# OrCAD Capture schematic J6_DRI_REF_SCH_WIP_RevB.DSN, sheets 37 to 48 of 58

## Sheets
37 SH40 - VIDEO OUT FPD LINK: size B; rev: A
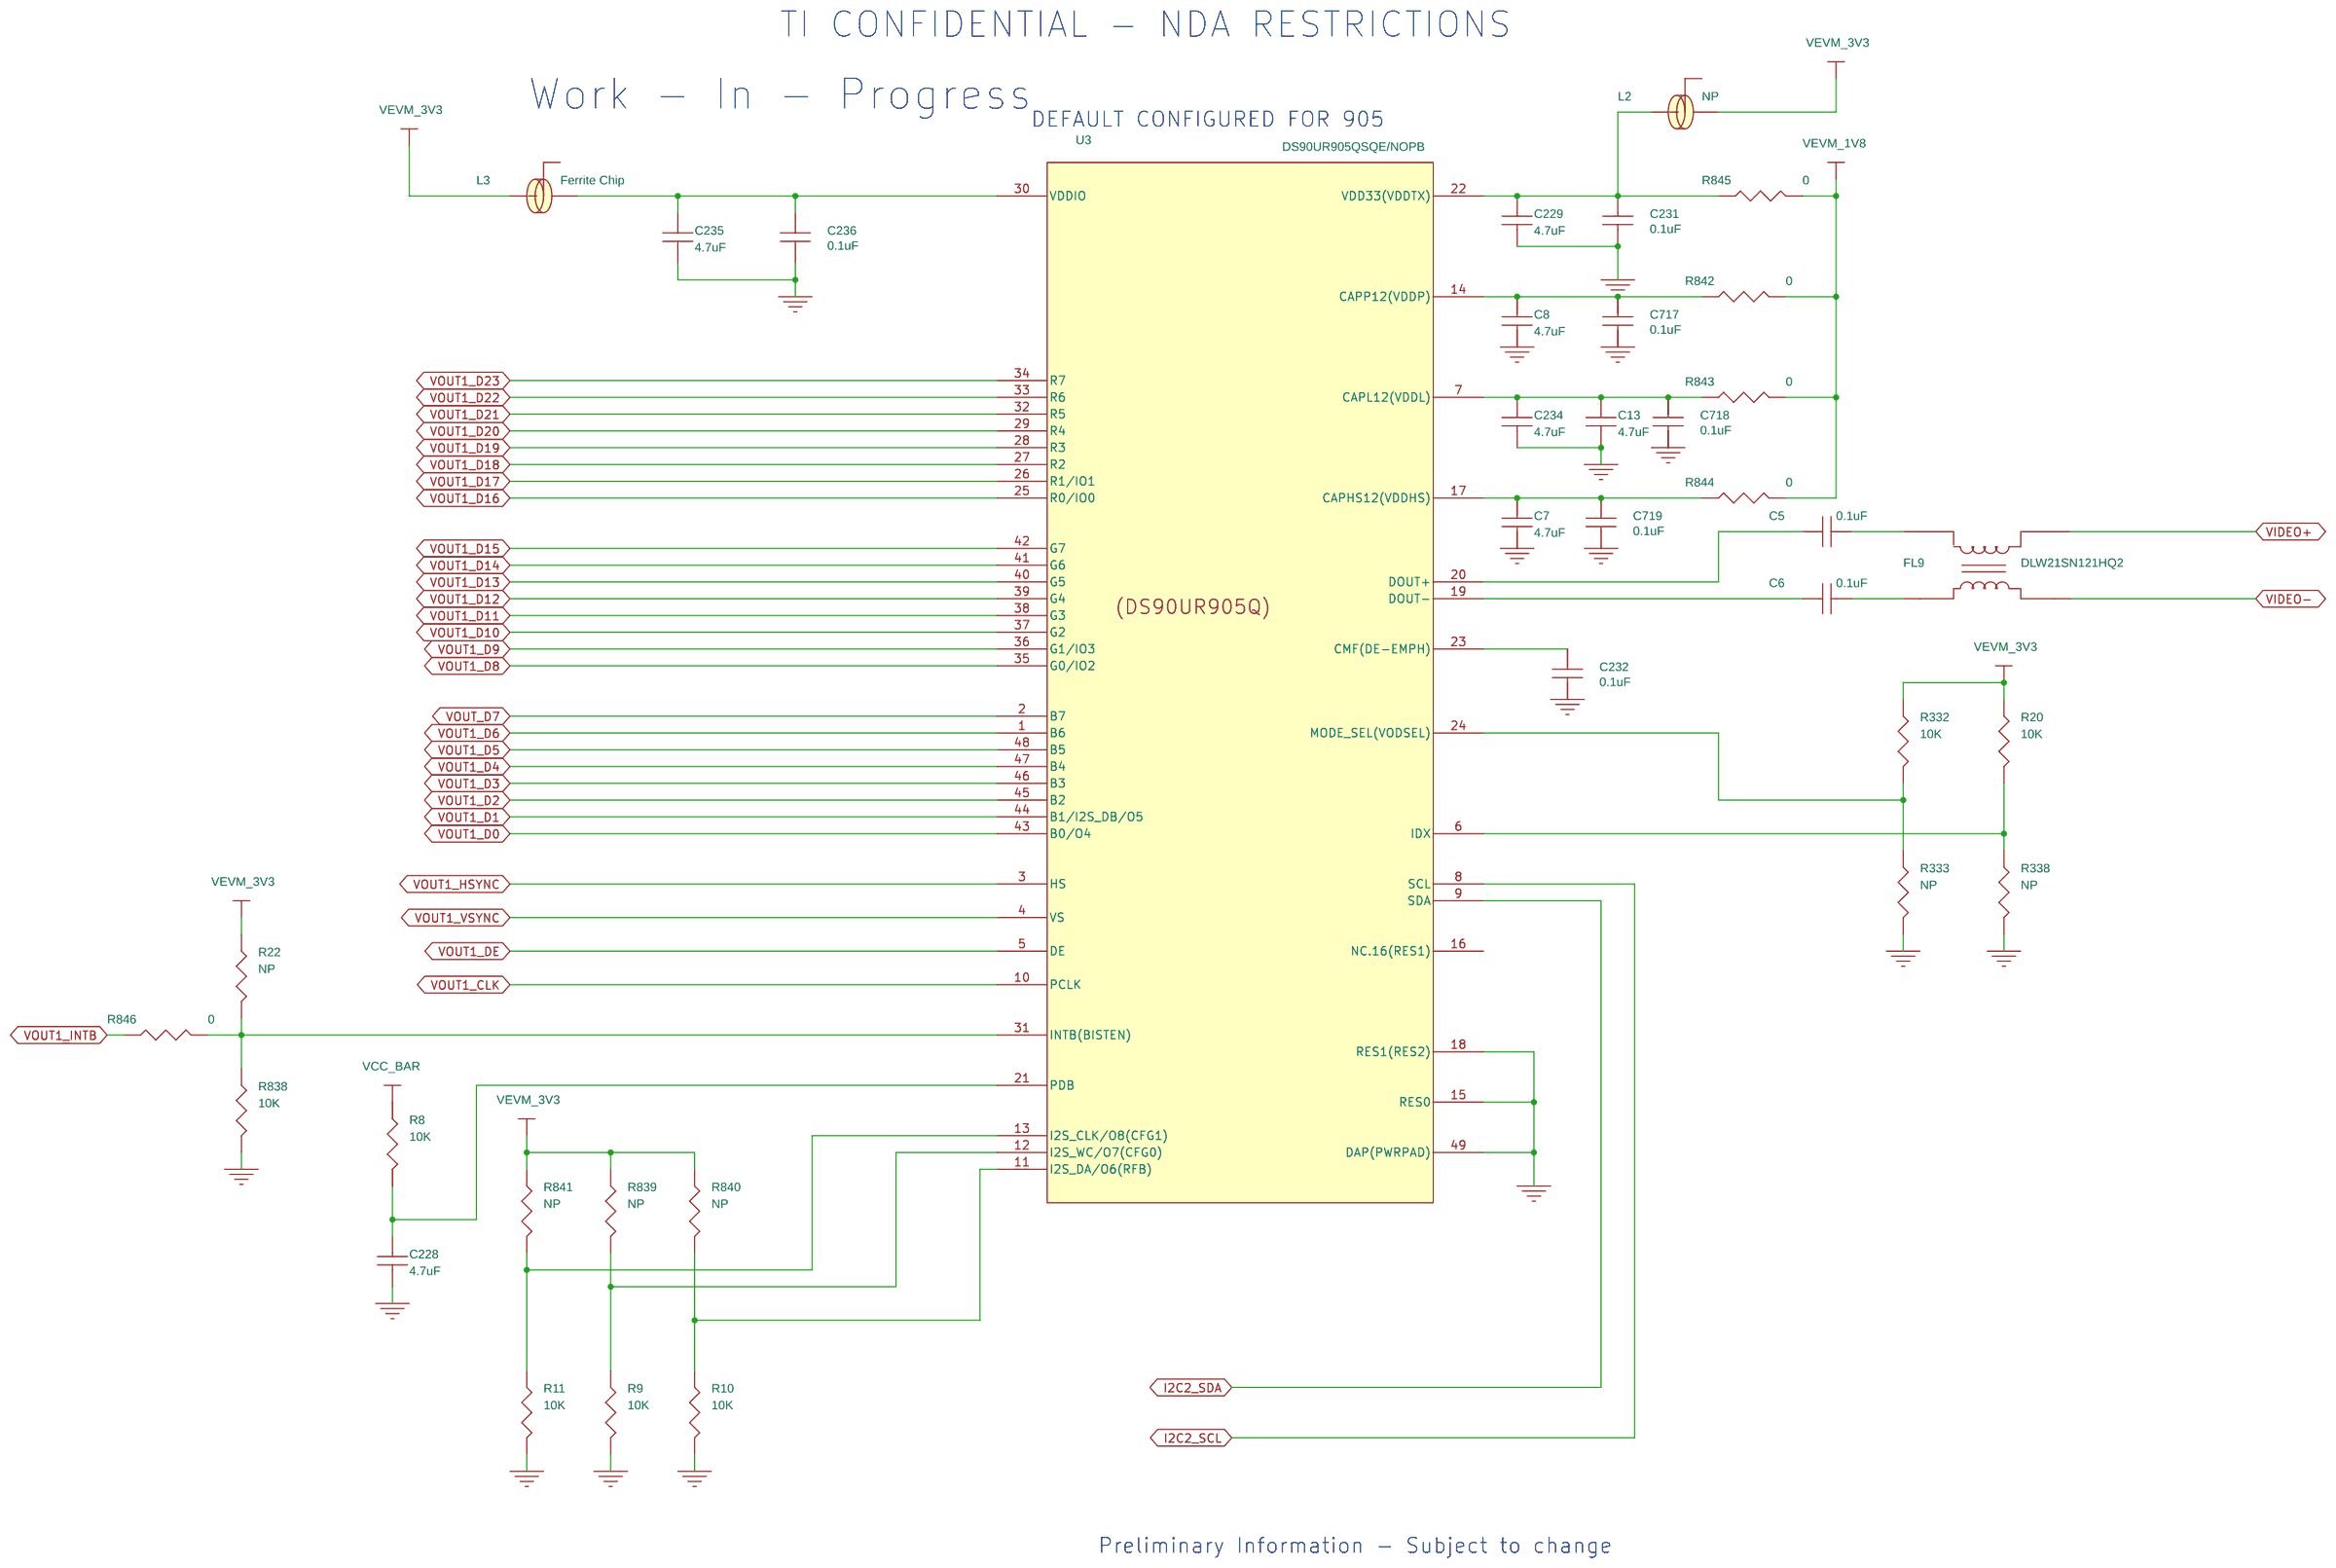
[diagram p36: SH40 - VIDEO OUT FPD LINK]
38 SH41 - VIDEO IN: size B; rev: A
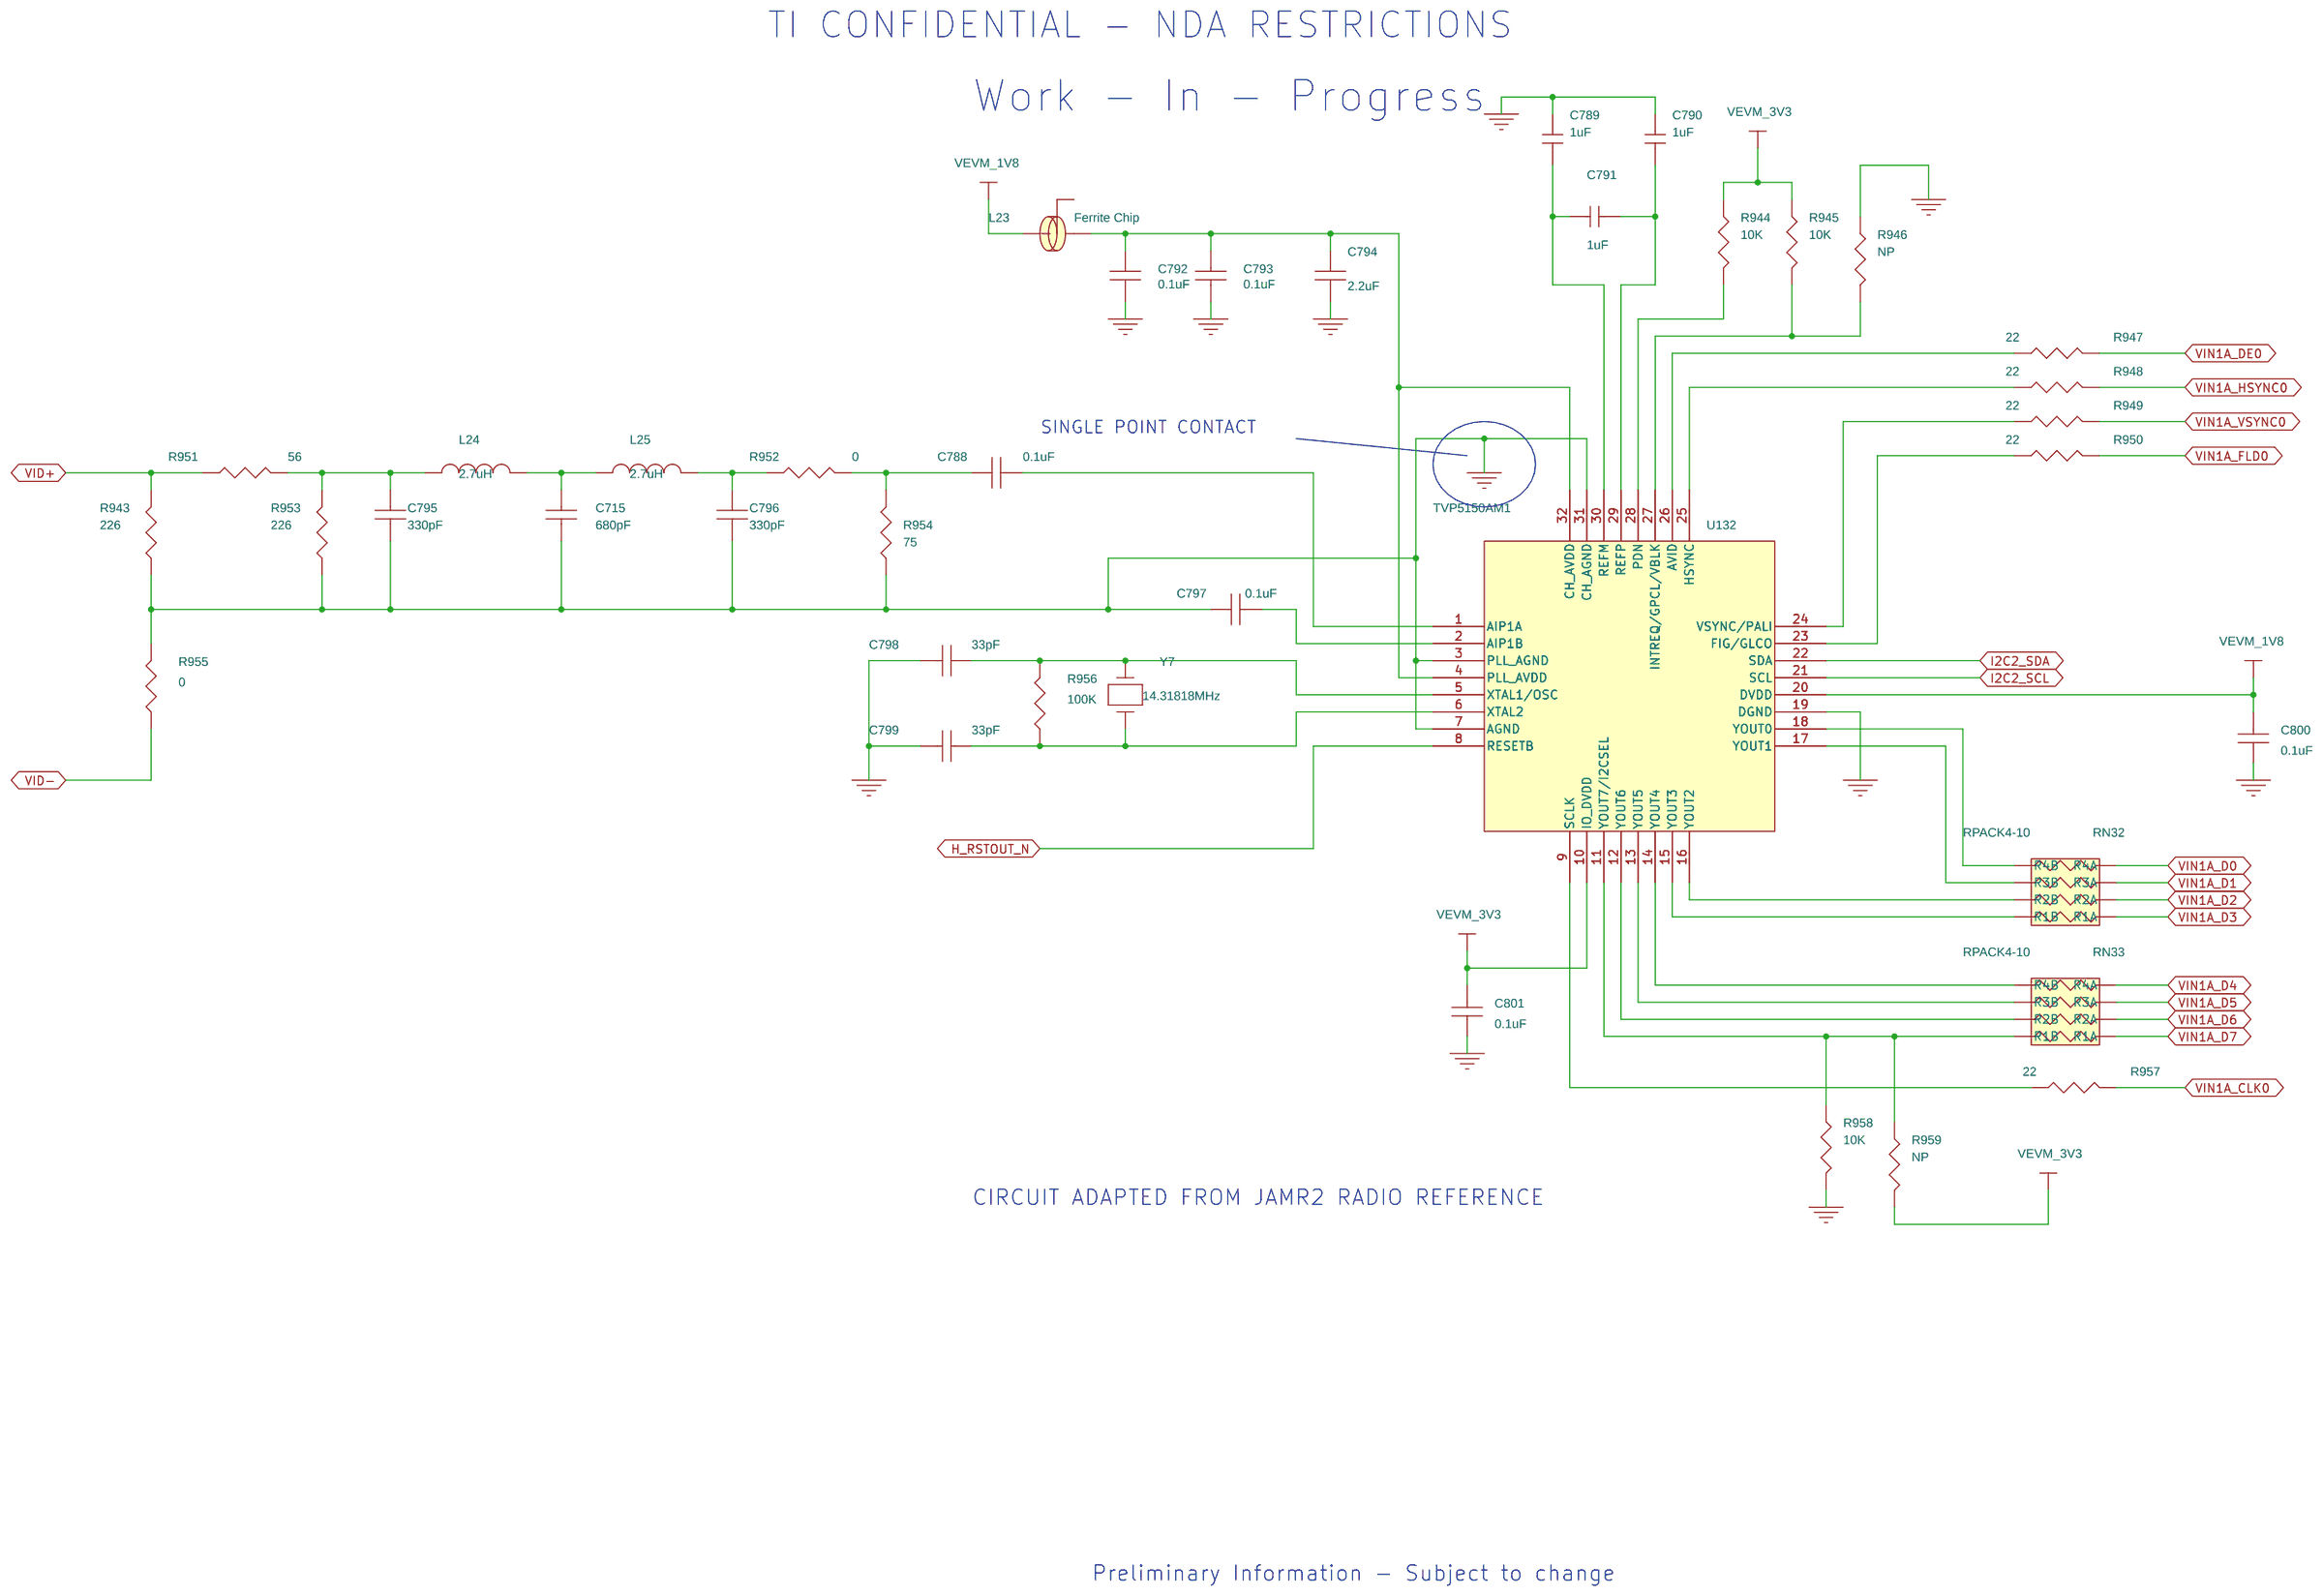
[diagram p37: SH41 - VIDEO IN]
39 SH42 - AUDIO CO-DEC: size B; rev: A
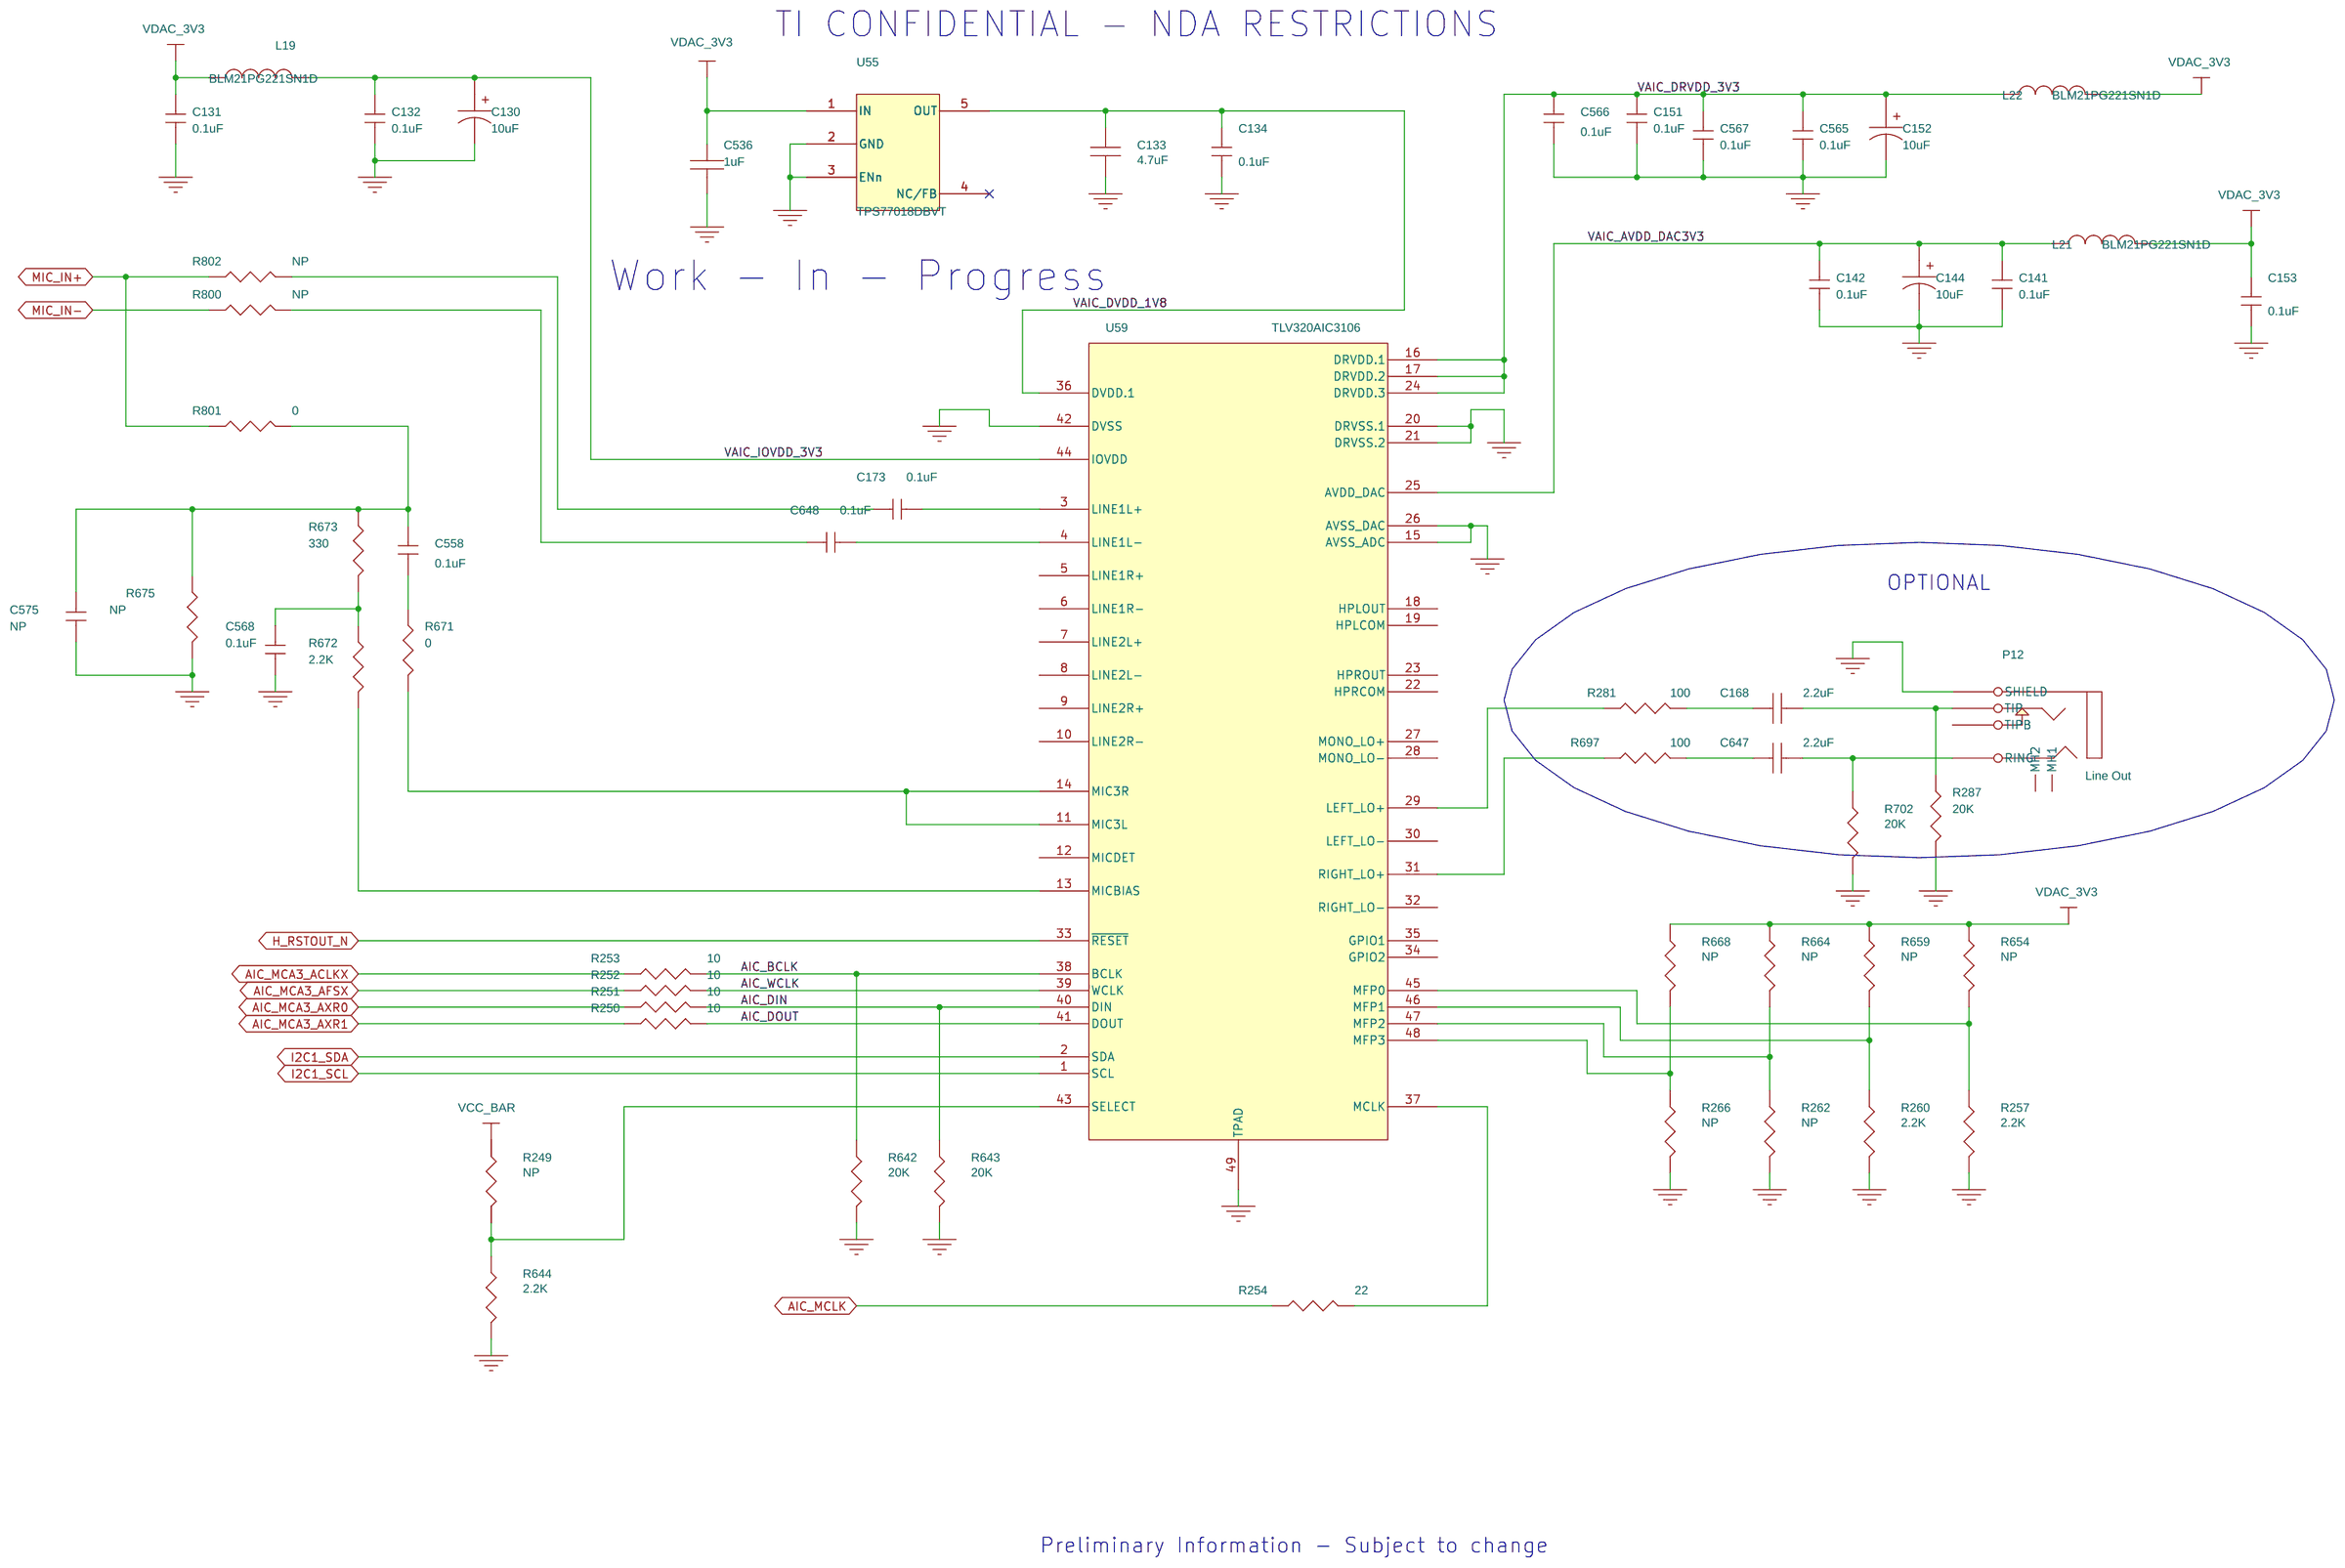
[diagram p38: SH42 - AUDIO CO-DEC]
40 SH43 - PMIC CONTROL: size B; rev: A
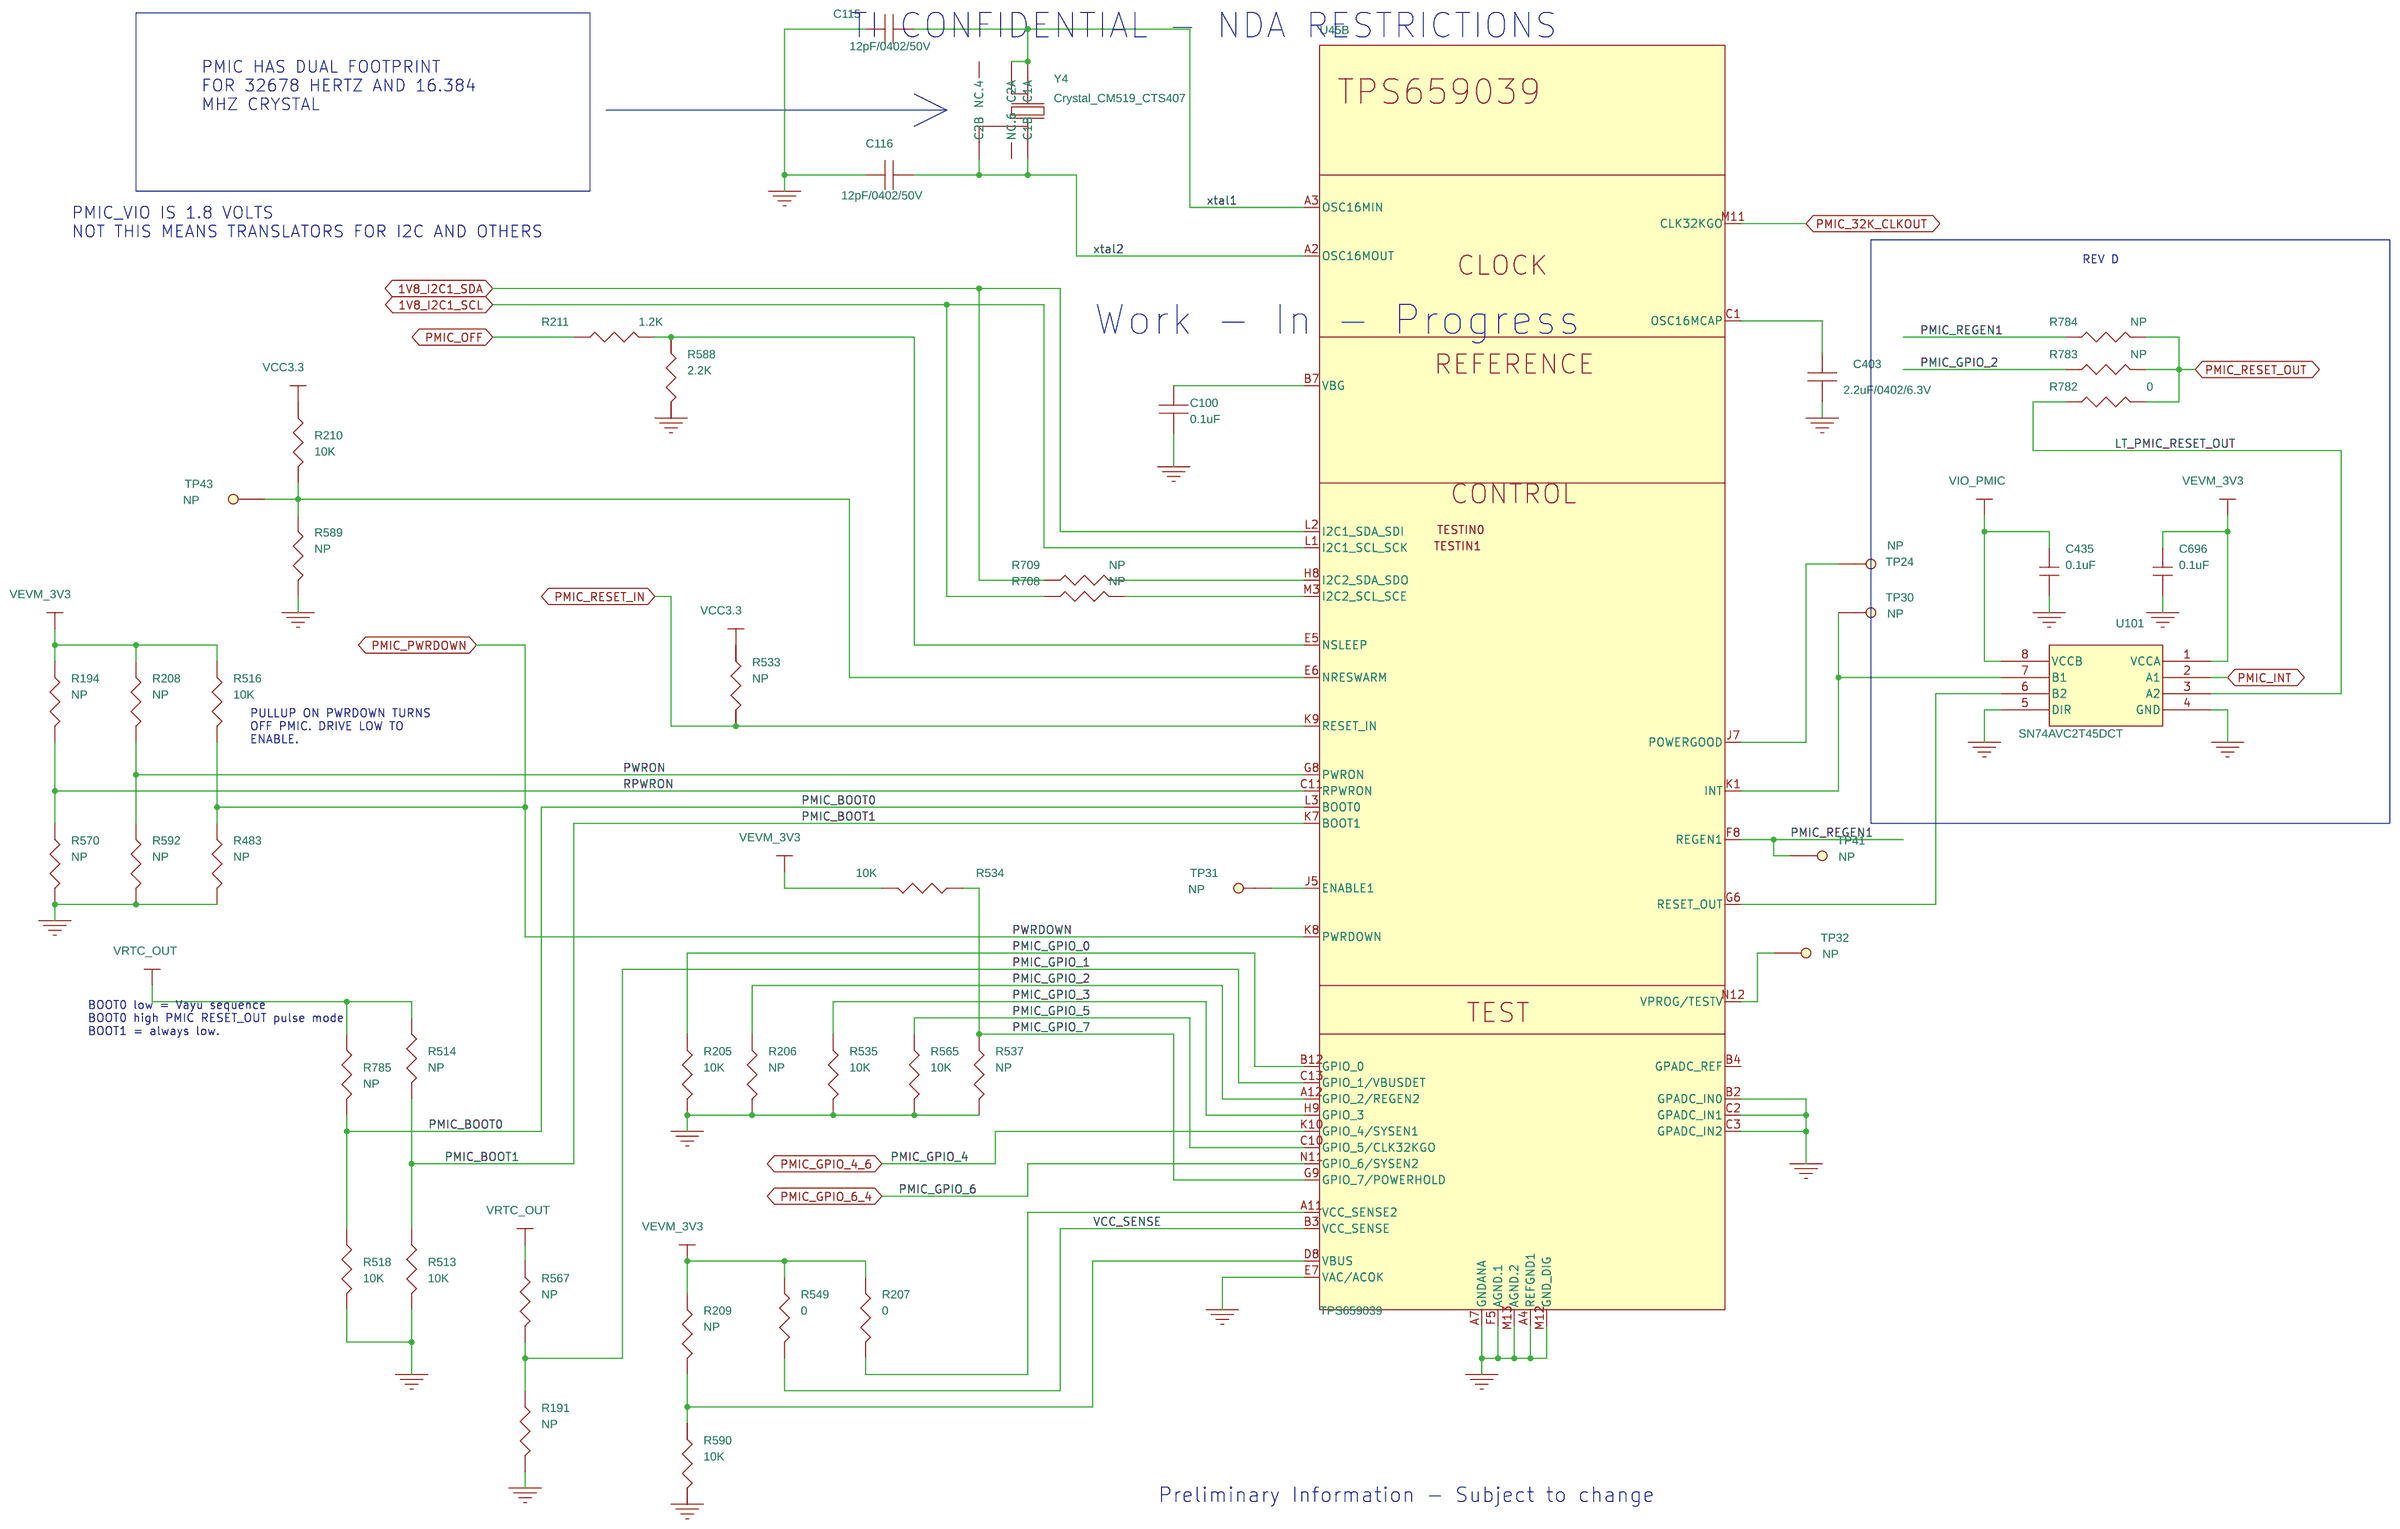
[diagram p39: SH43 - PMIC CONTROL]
41 SH44 - PMIC LDOS: size B; rev: A
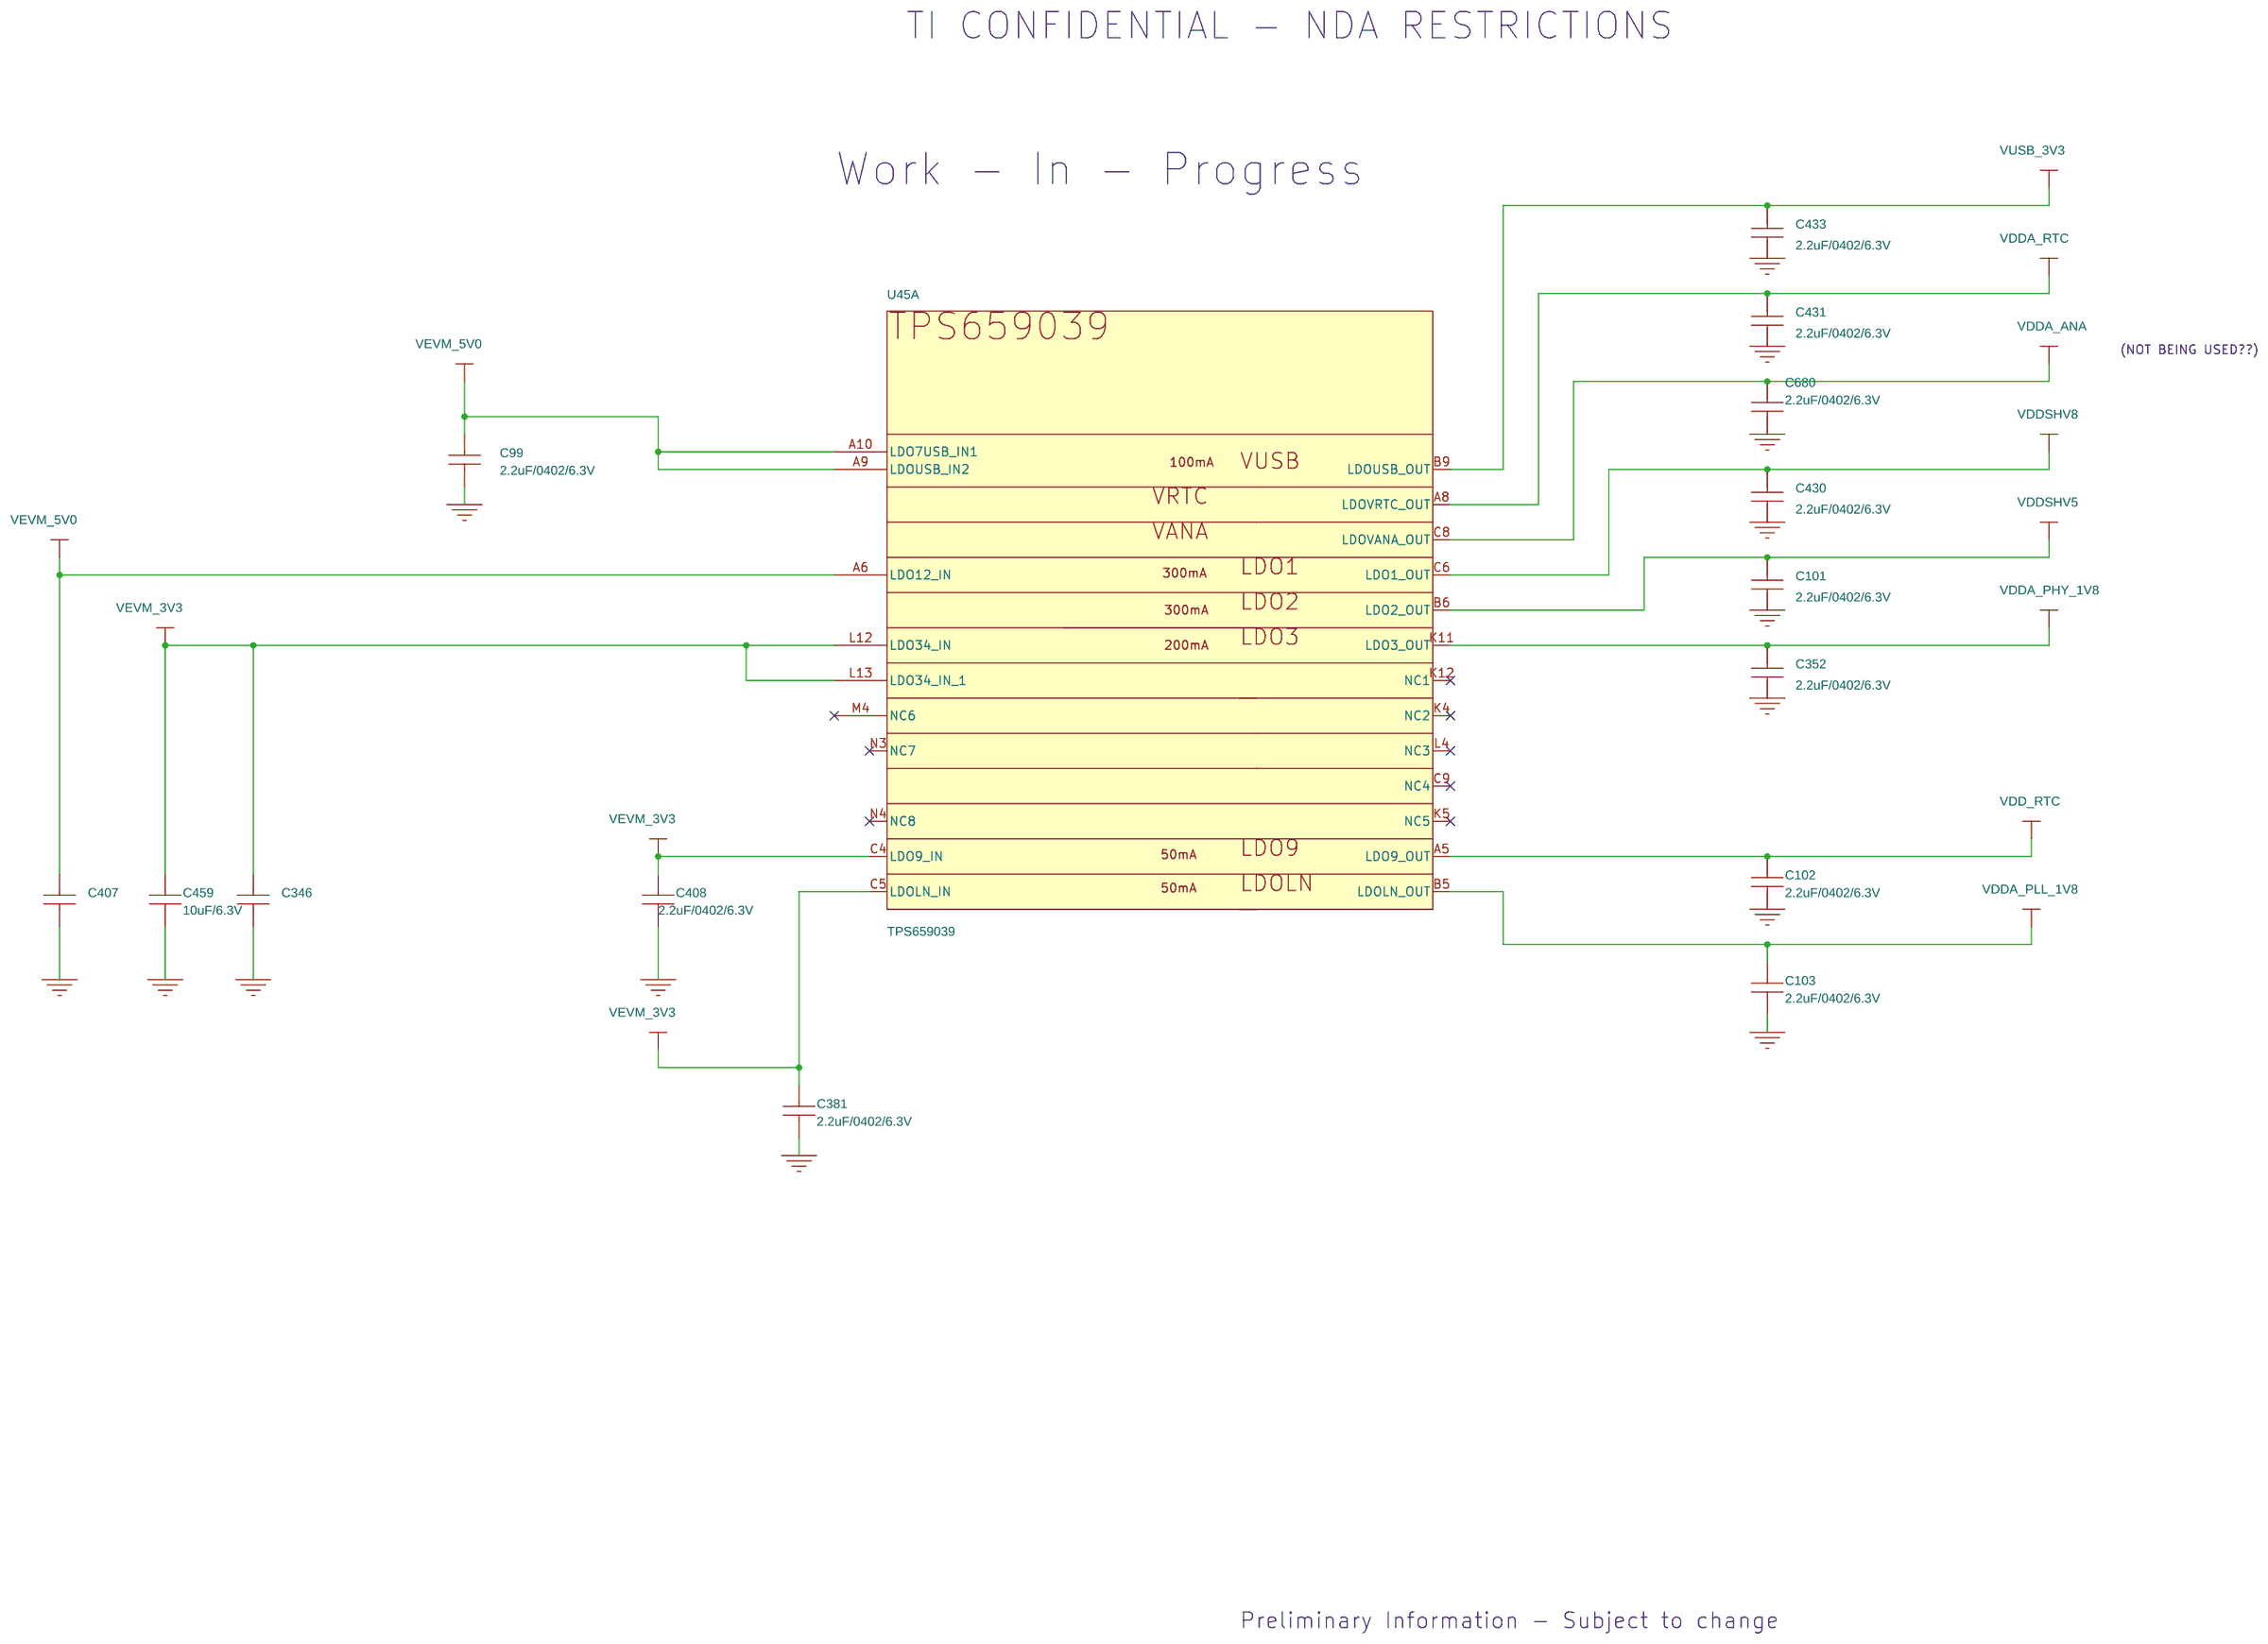
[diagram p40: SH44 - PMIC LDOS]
42 SH45 - PMIC SMPS1-5: size B; rev: A
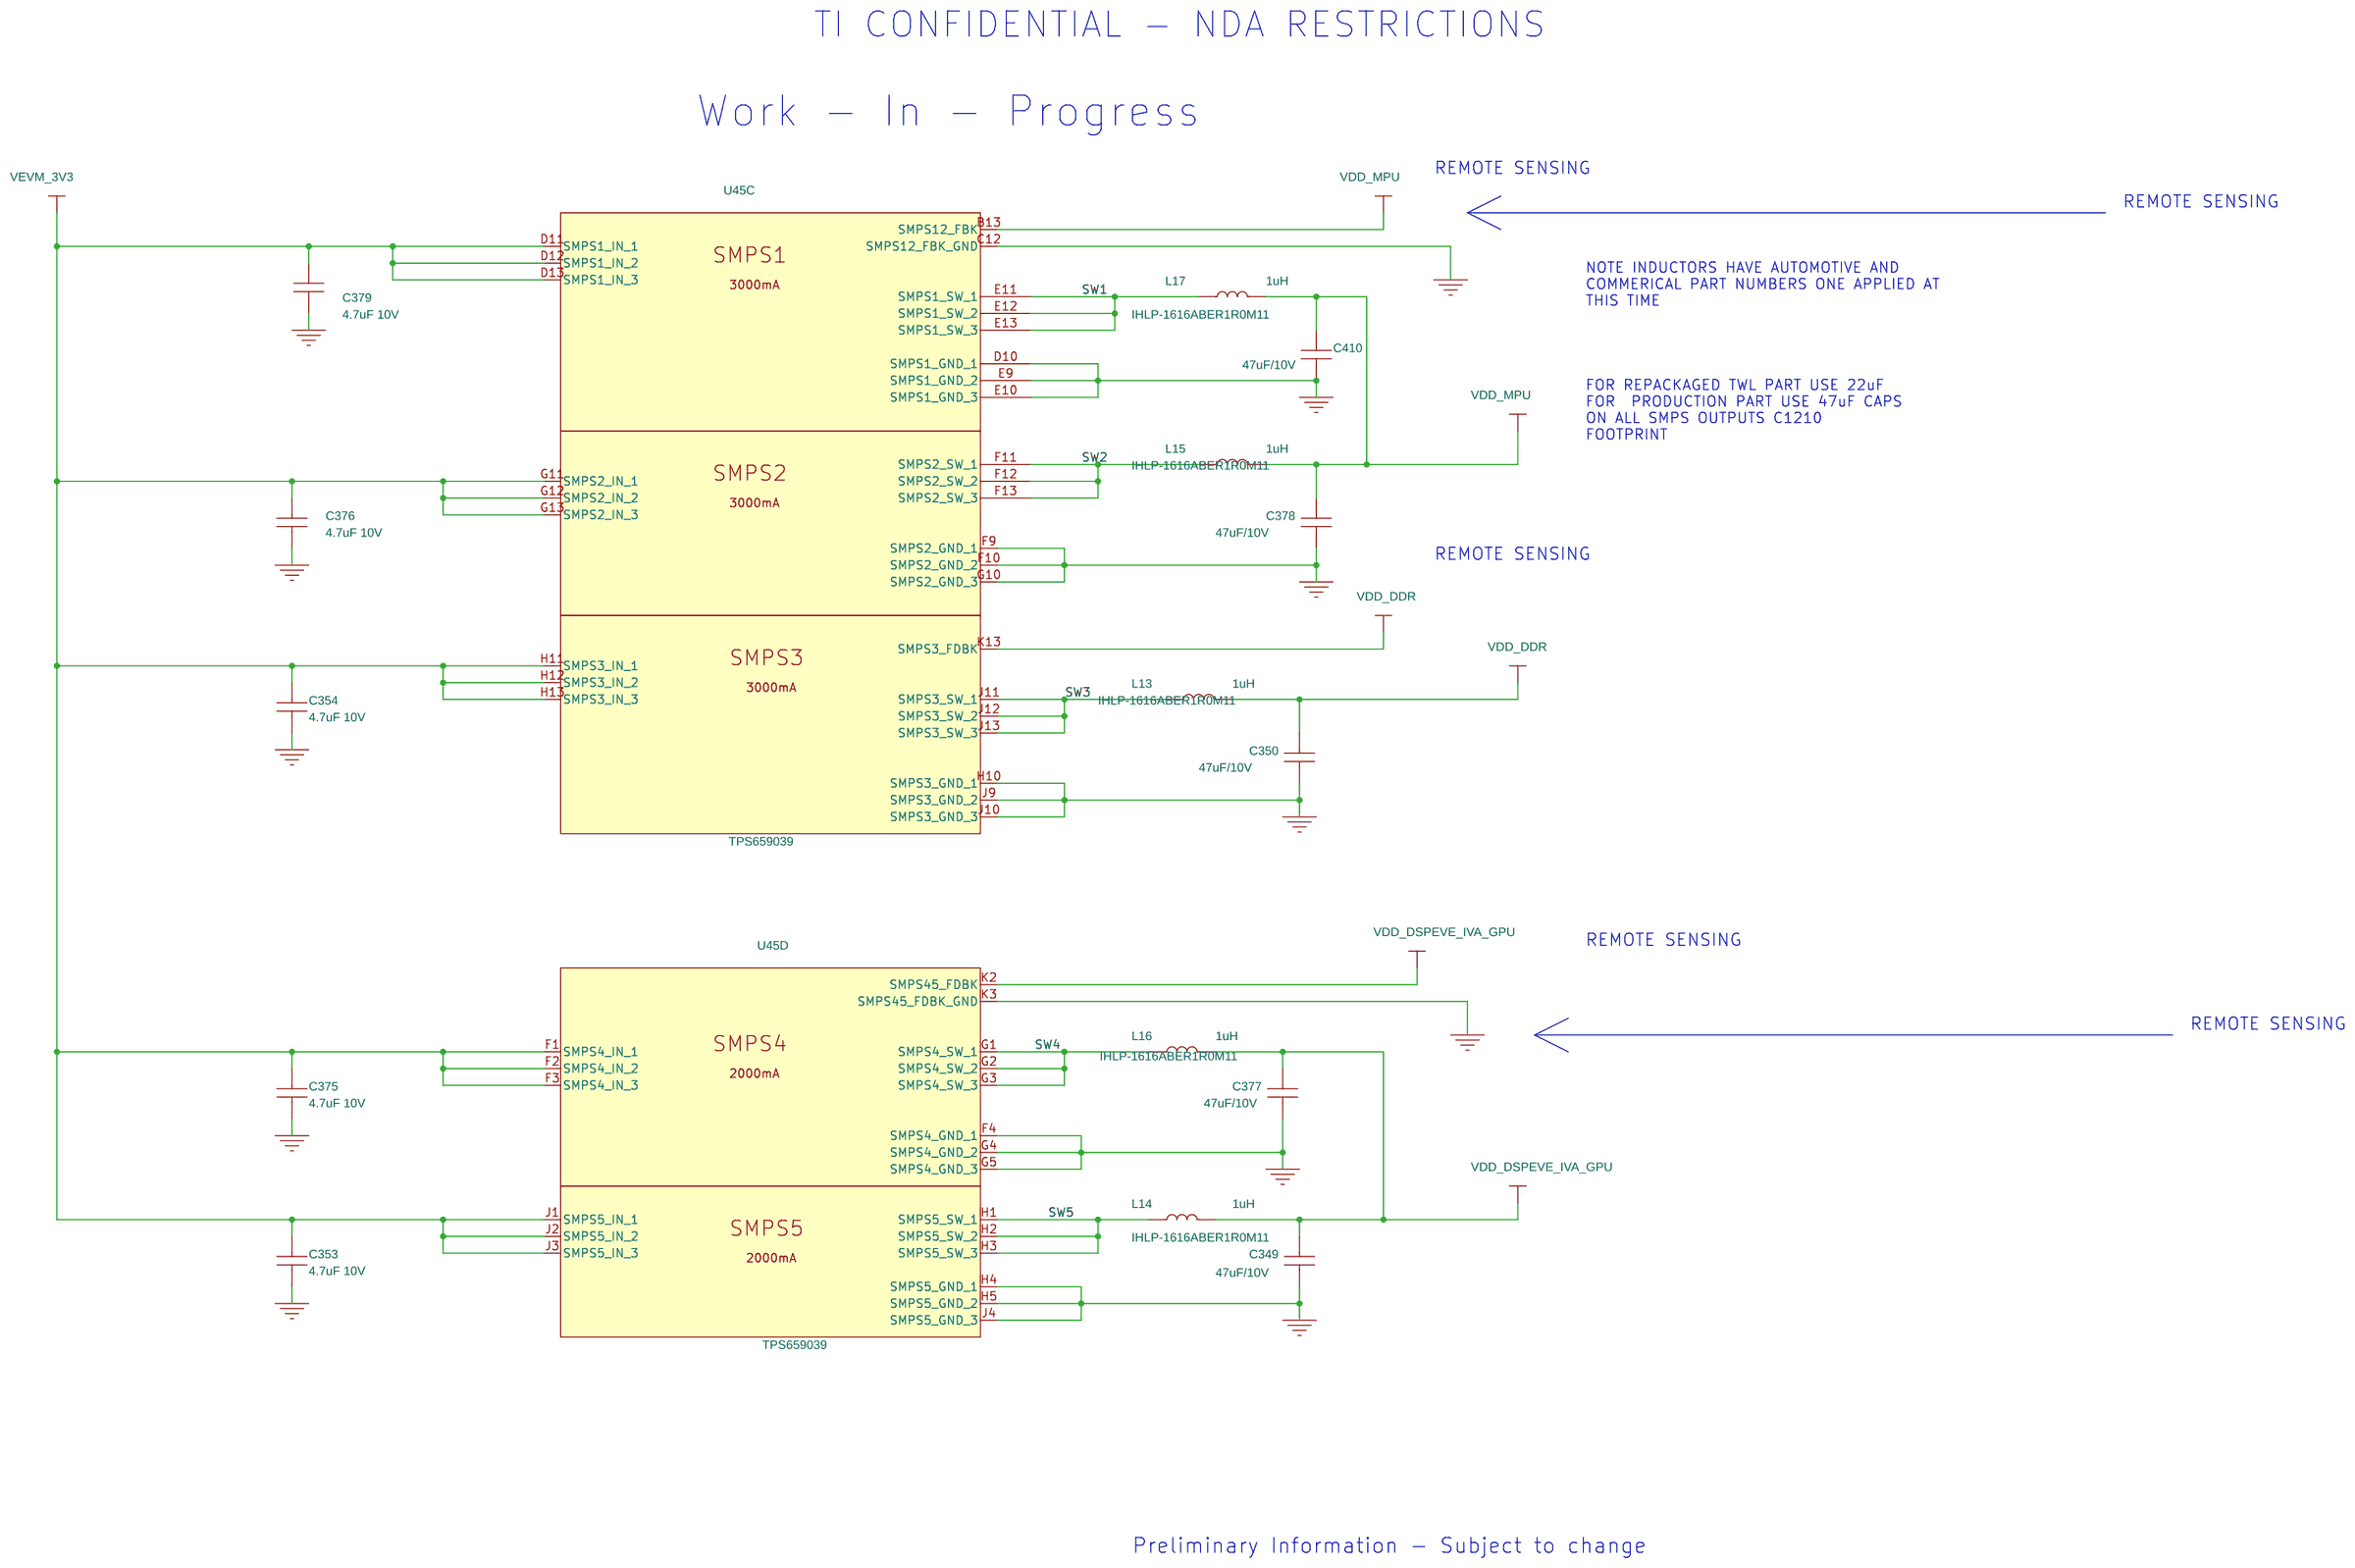
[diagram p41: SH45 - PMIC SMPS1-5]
43 SH46 - PMIC SMPS6-9 INT POWER: size B; rev: A
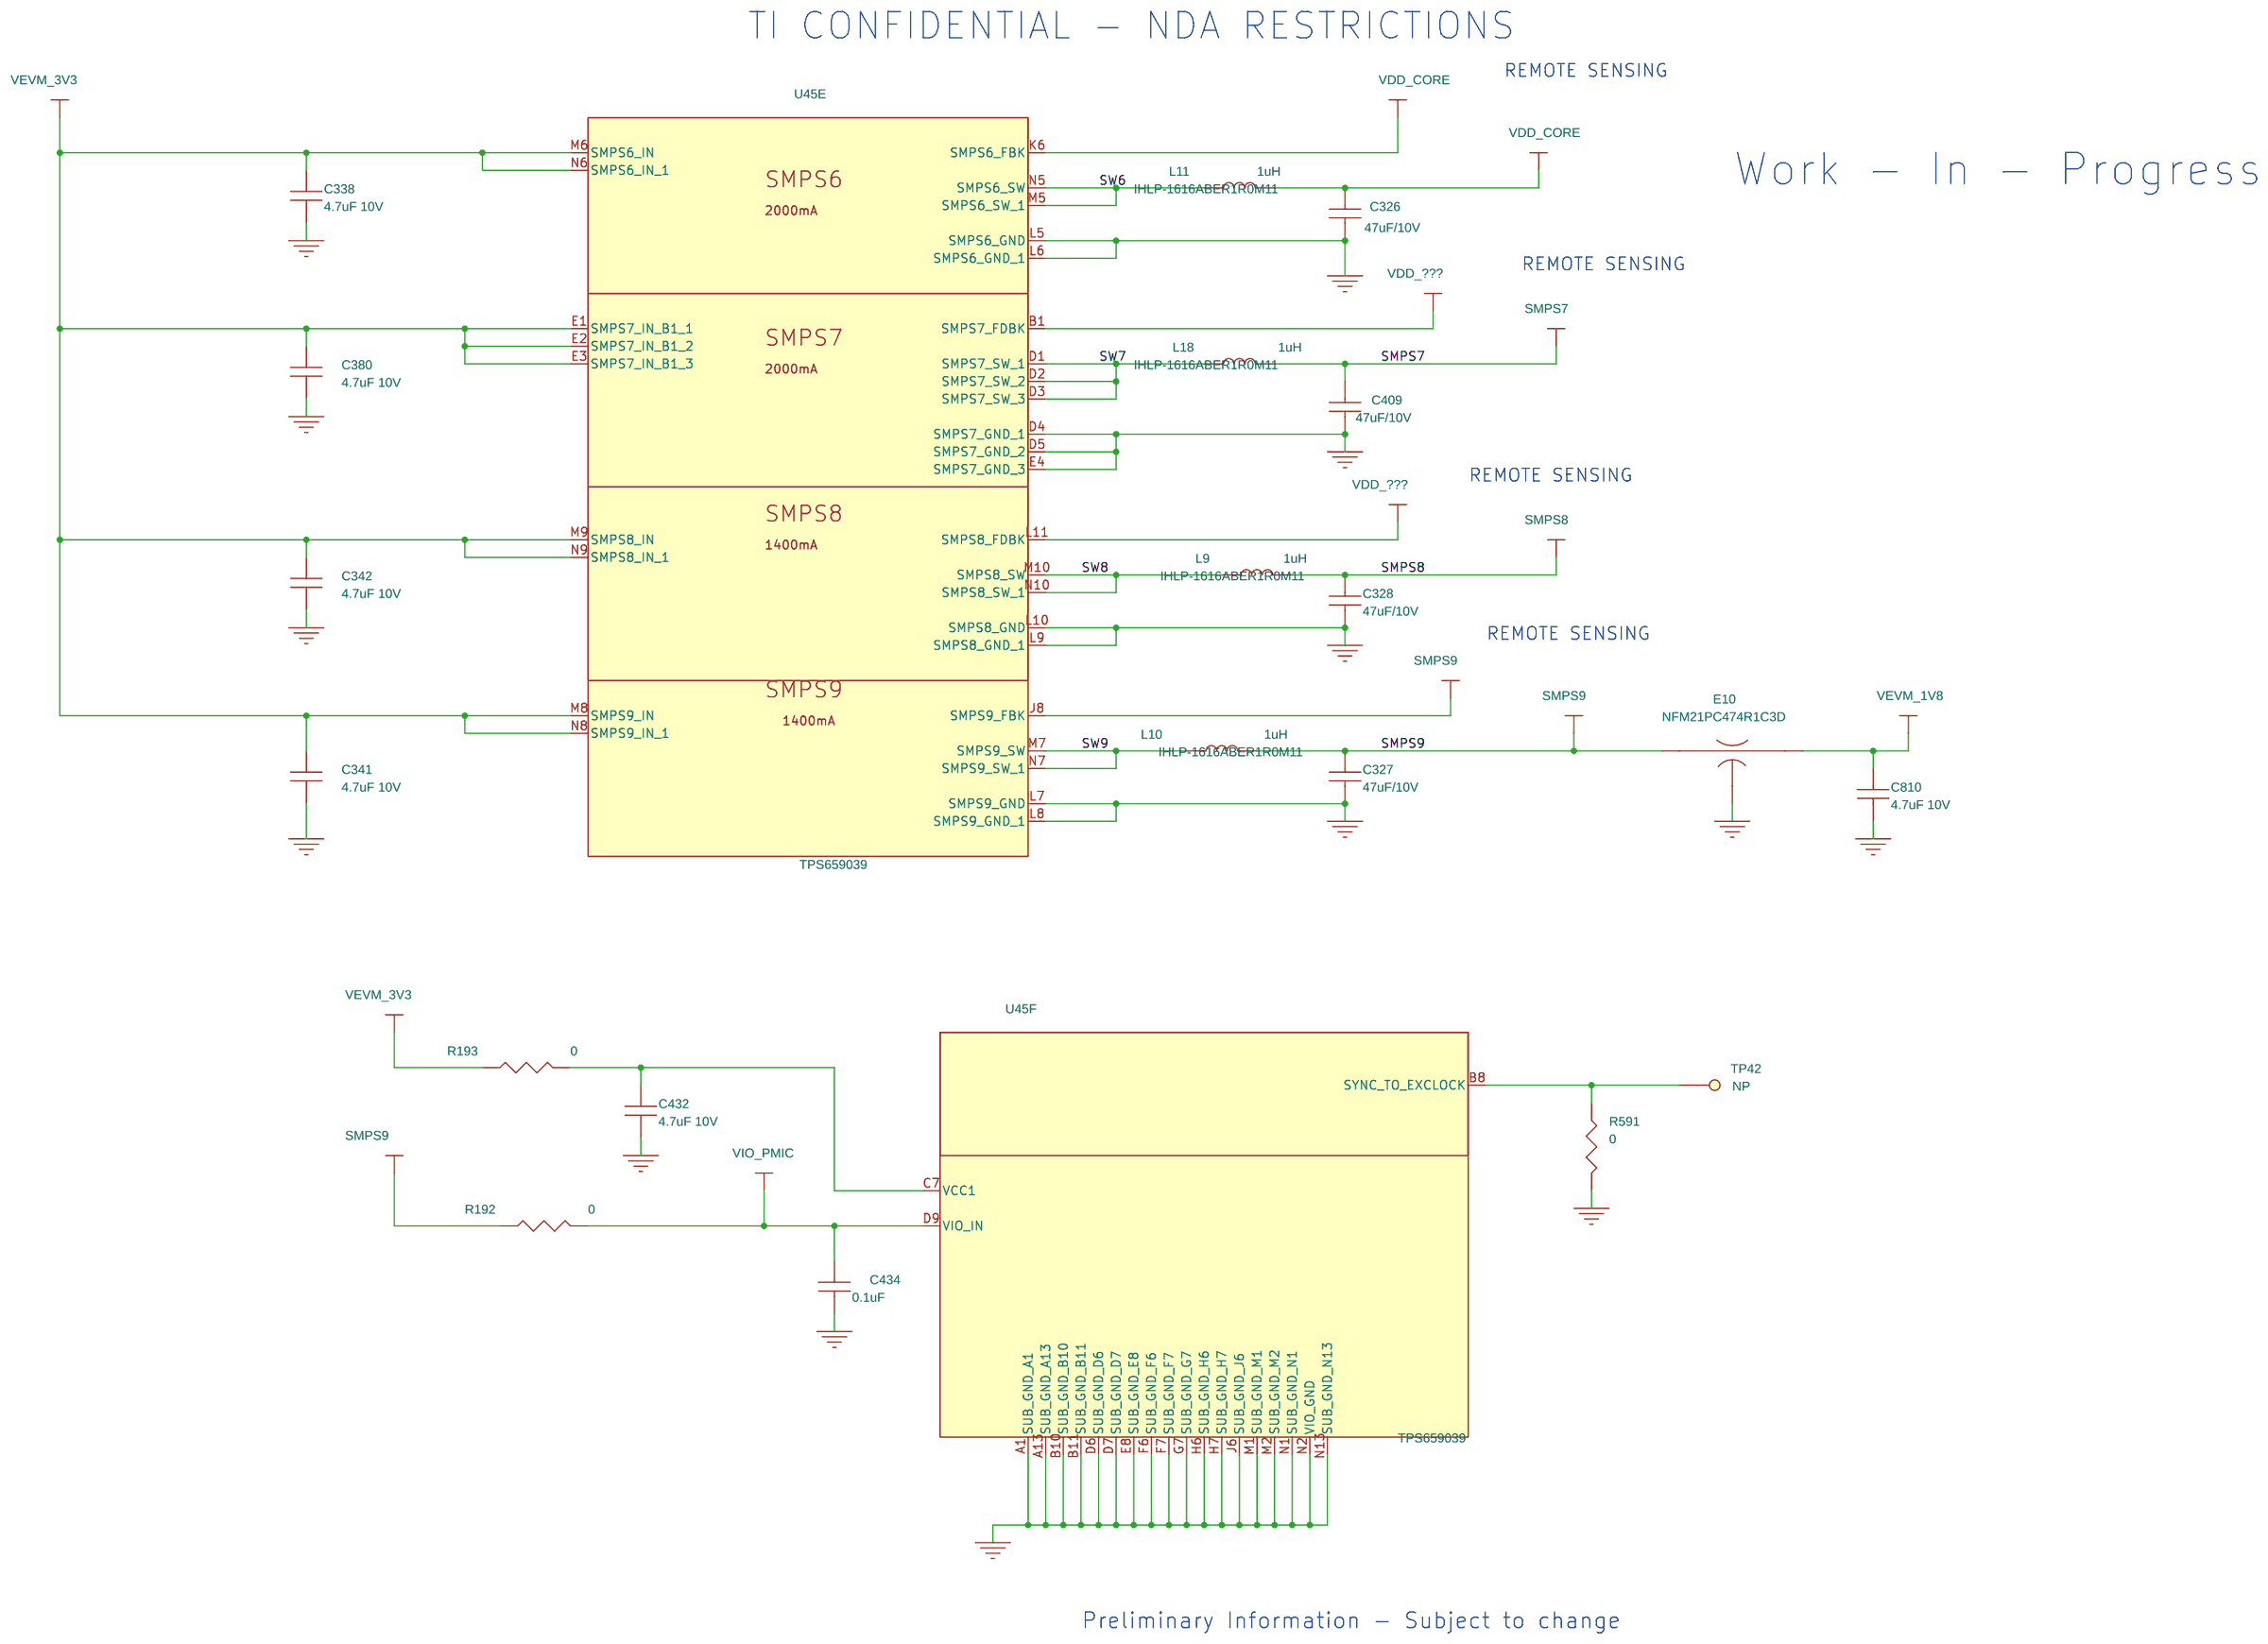
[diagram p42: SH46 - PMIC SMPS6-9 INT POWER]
44 SH47 - RESET GENERATION: size B; rev: A
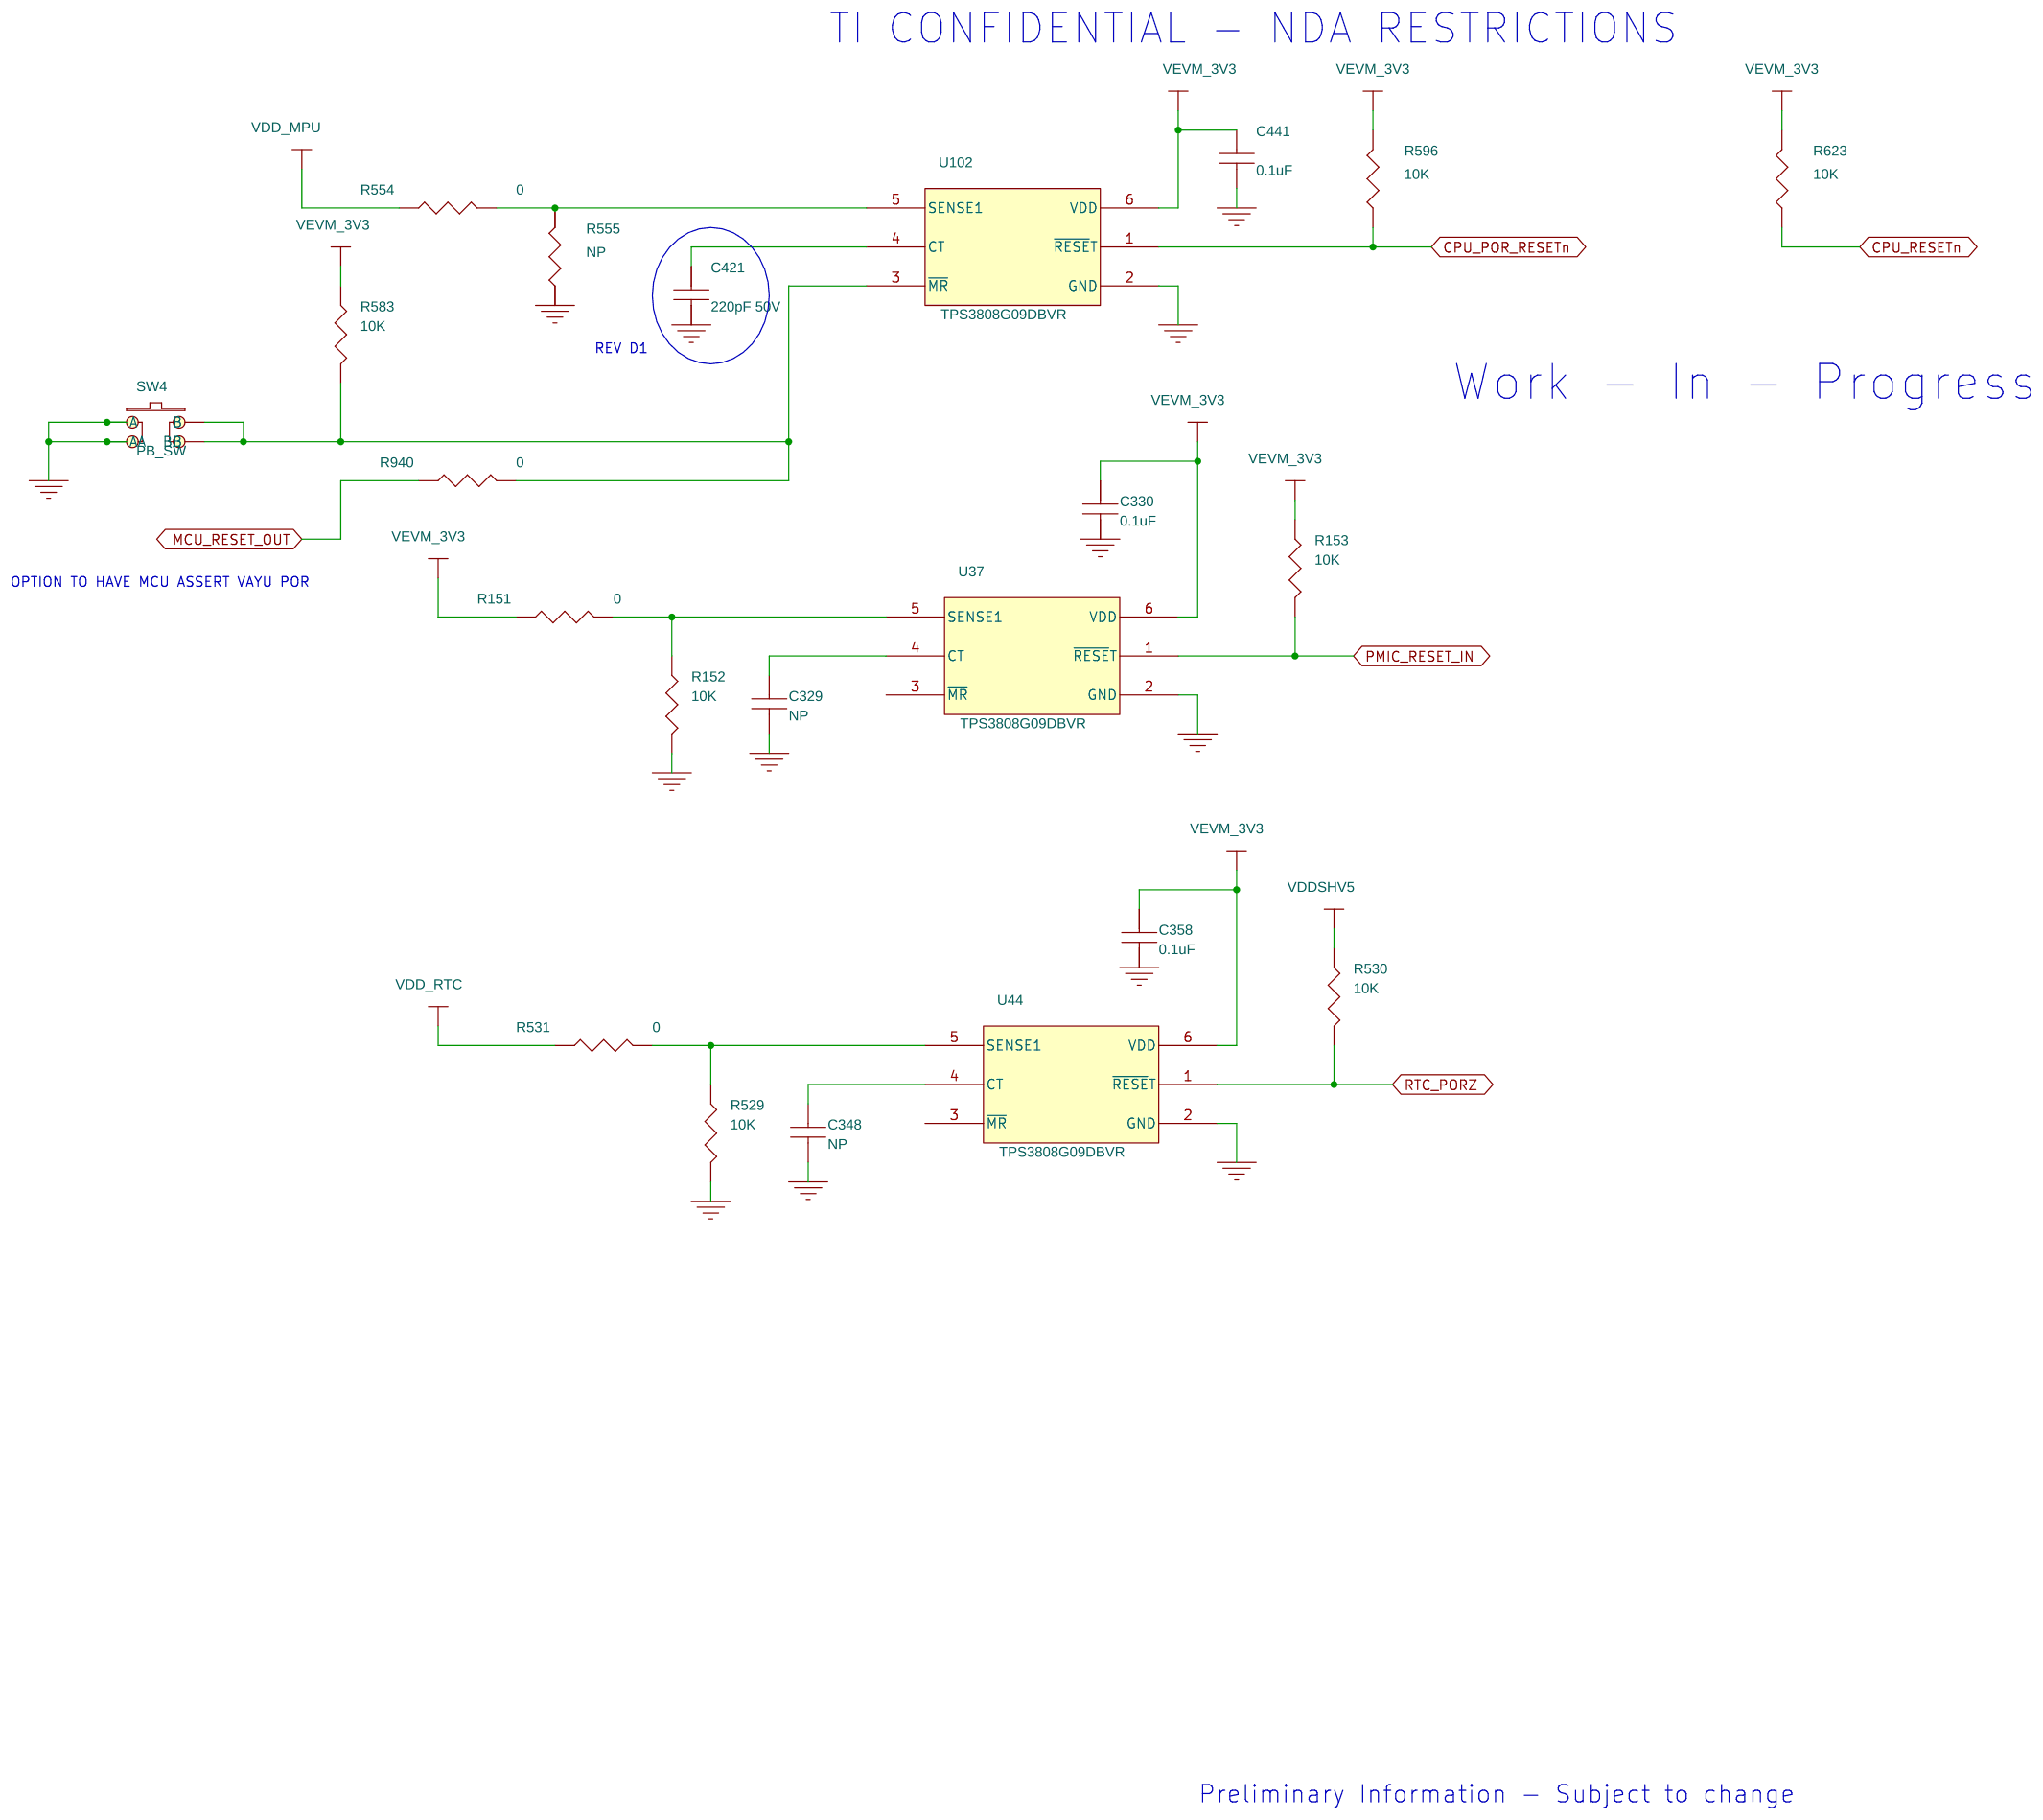
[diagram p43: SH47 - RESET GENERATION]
45 SH48 - SOC BOOT SETTINGS: size B; rev: A
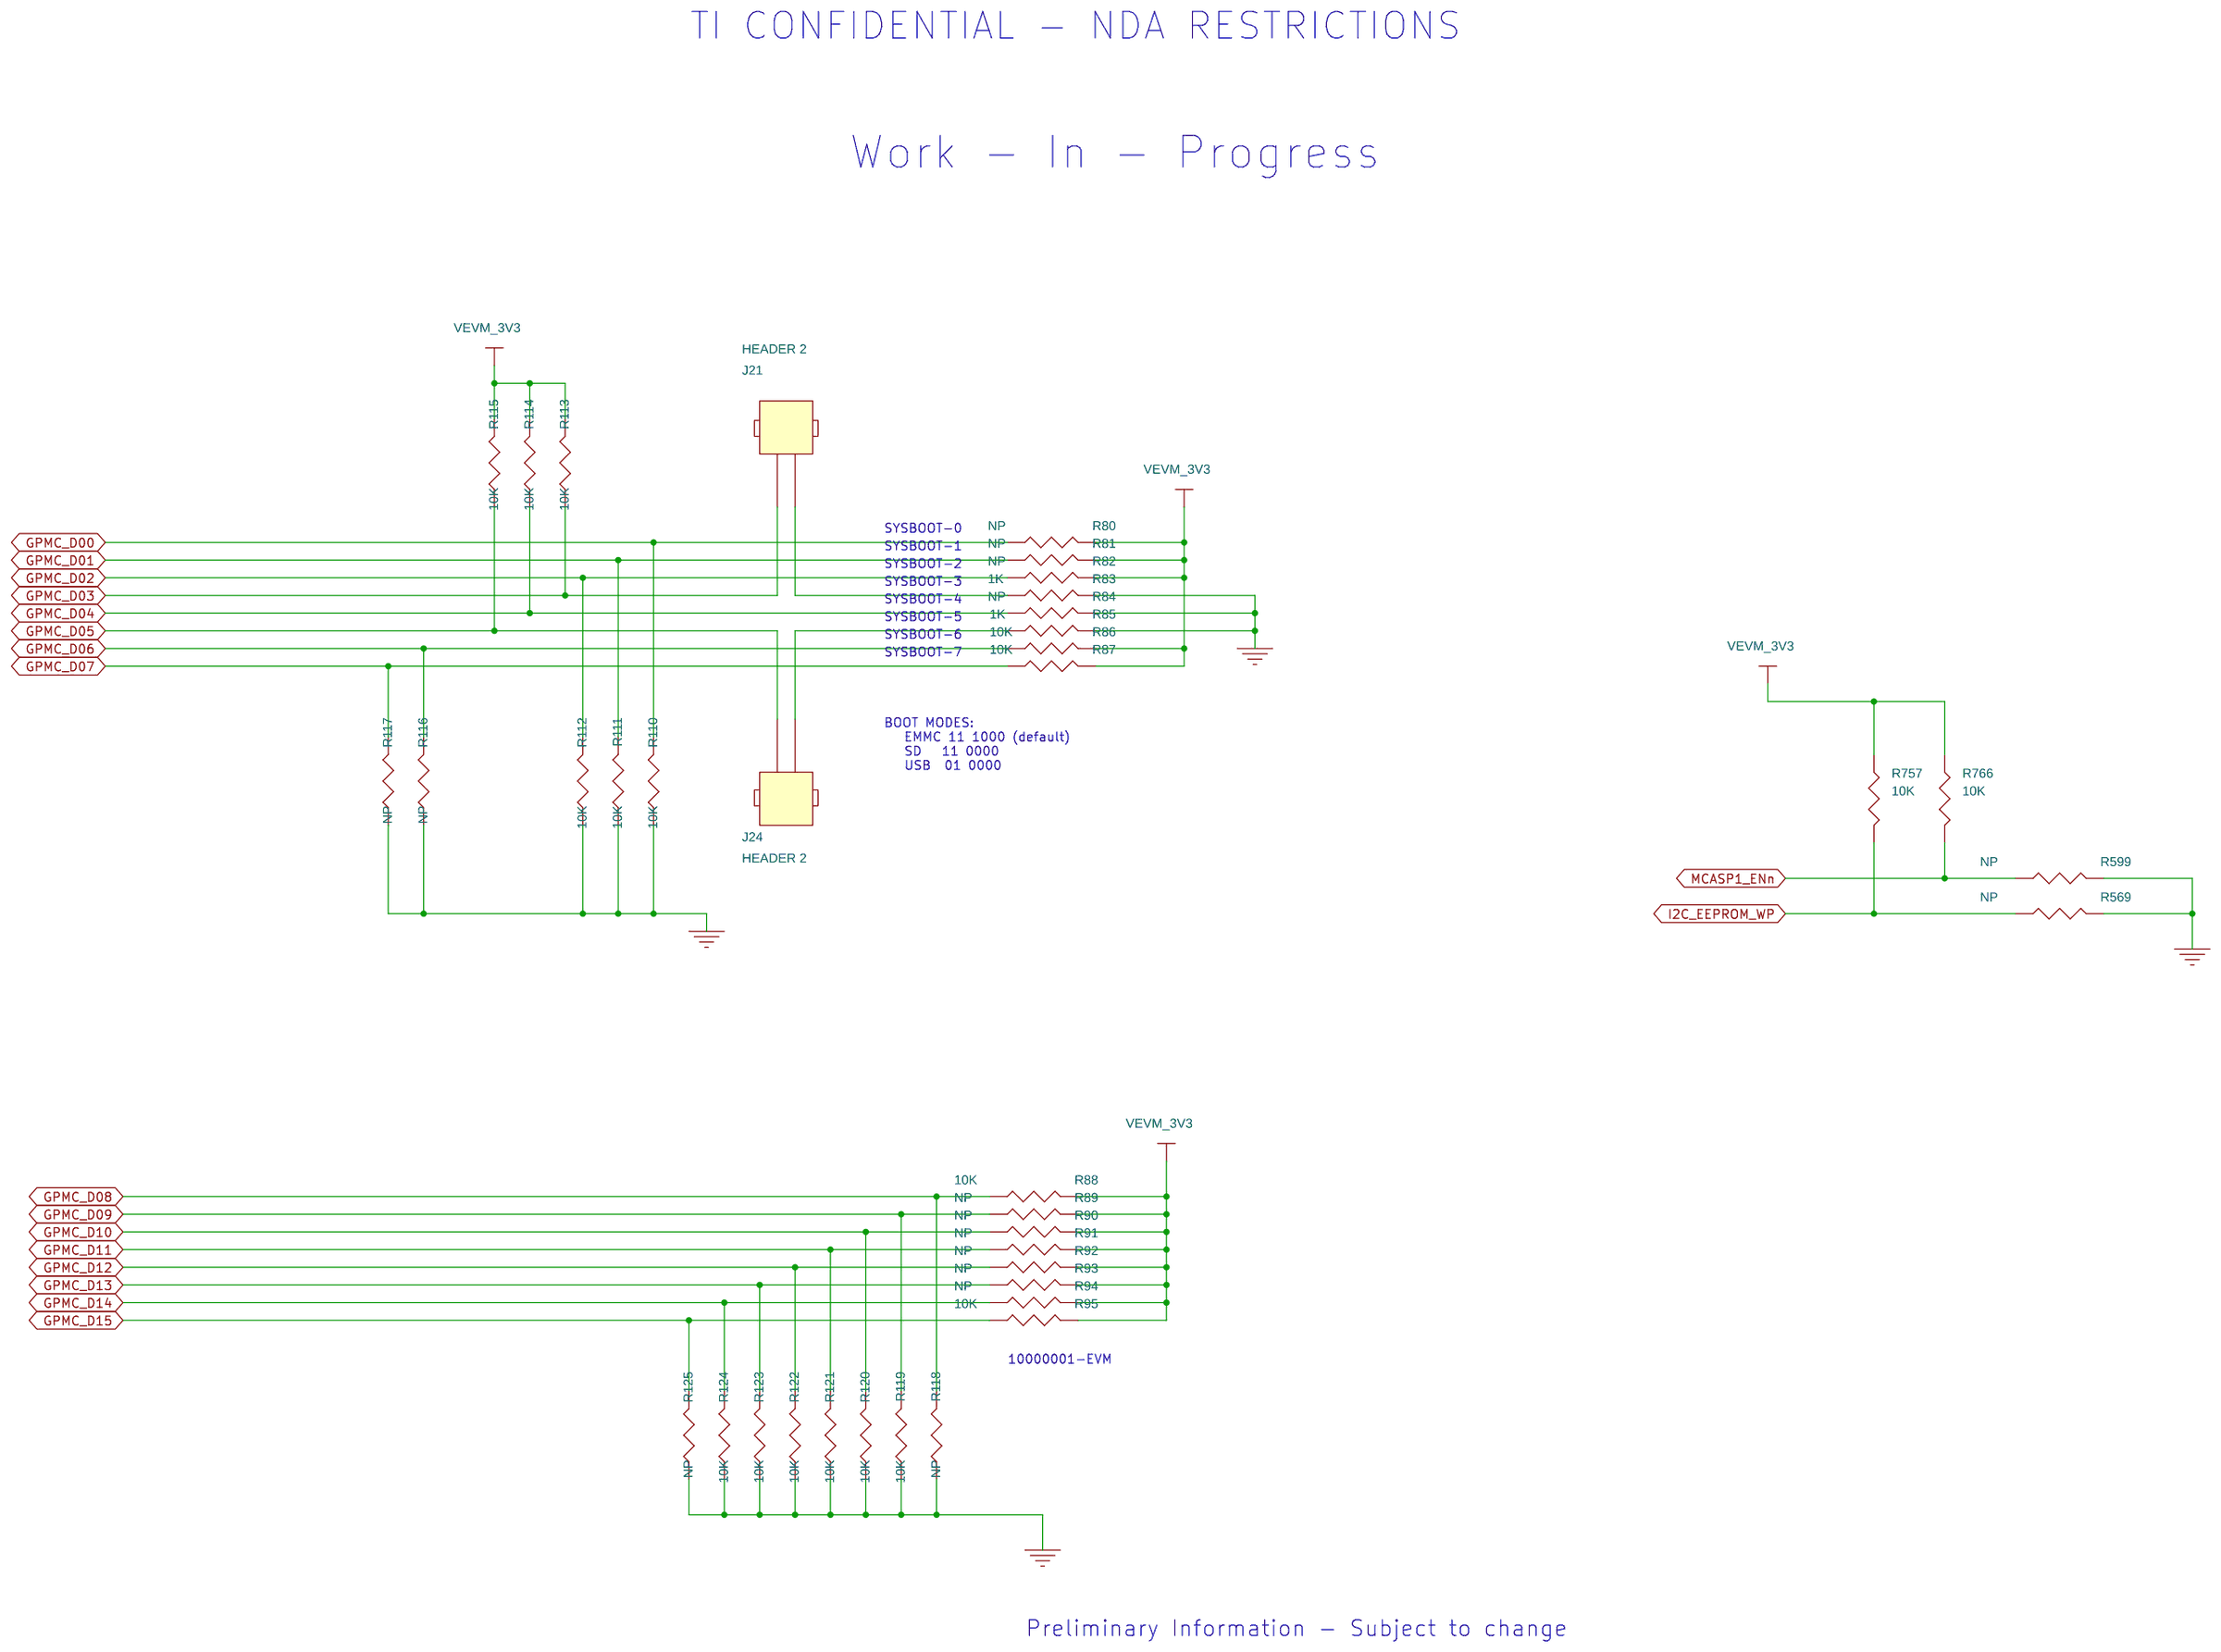
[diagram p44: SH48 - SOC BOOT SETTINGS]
46 SH49 - DEBUG: size B; rev: A
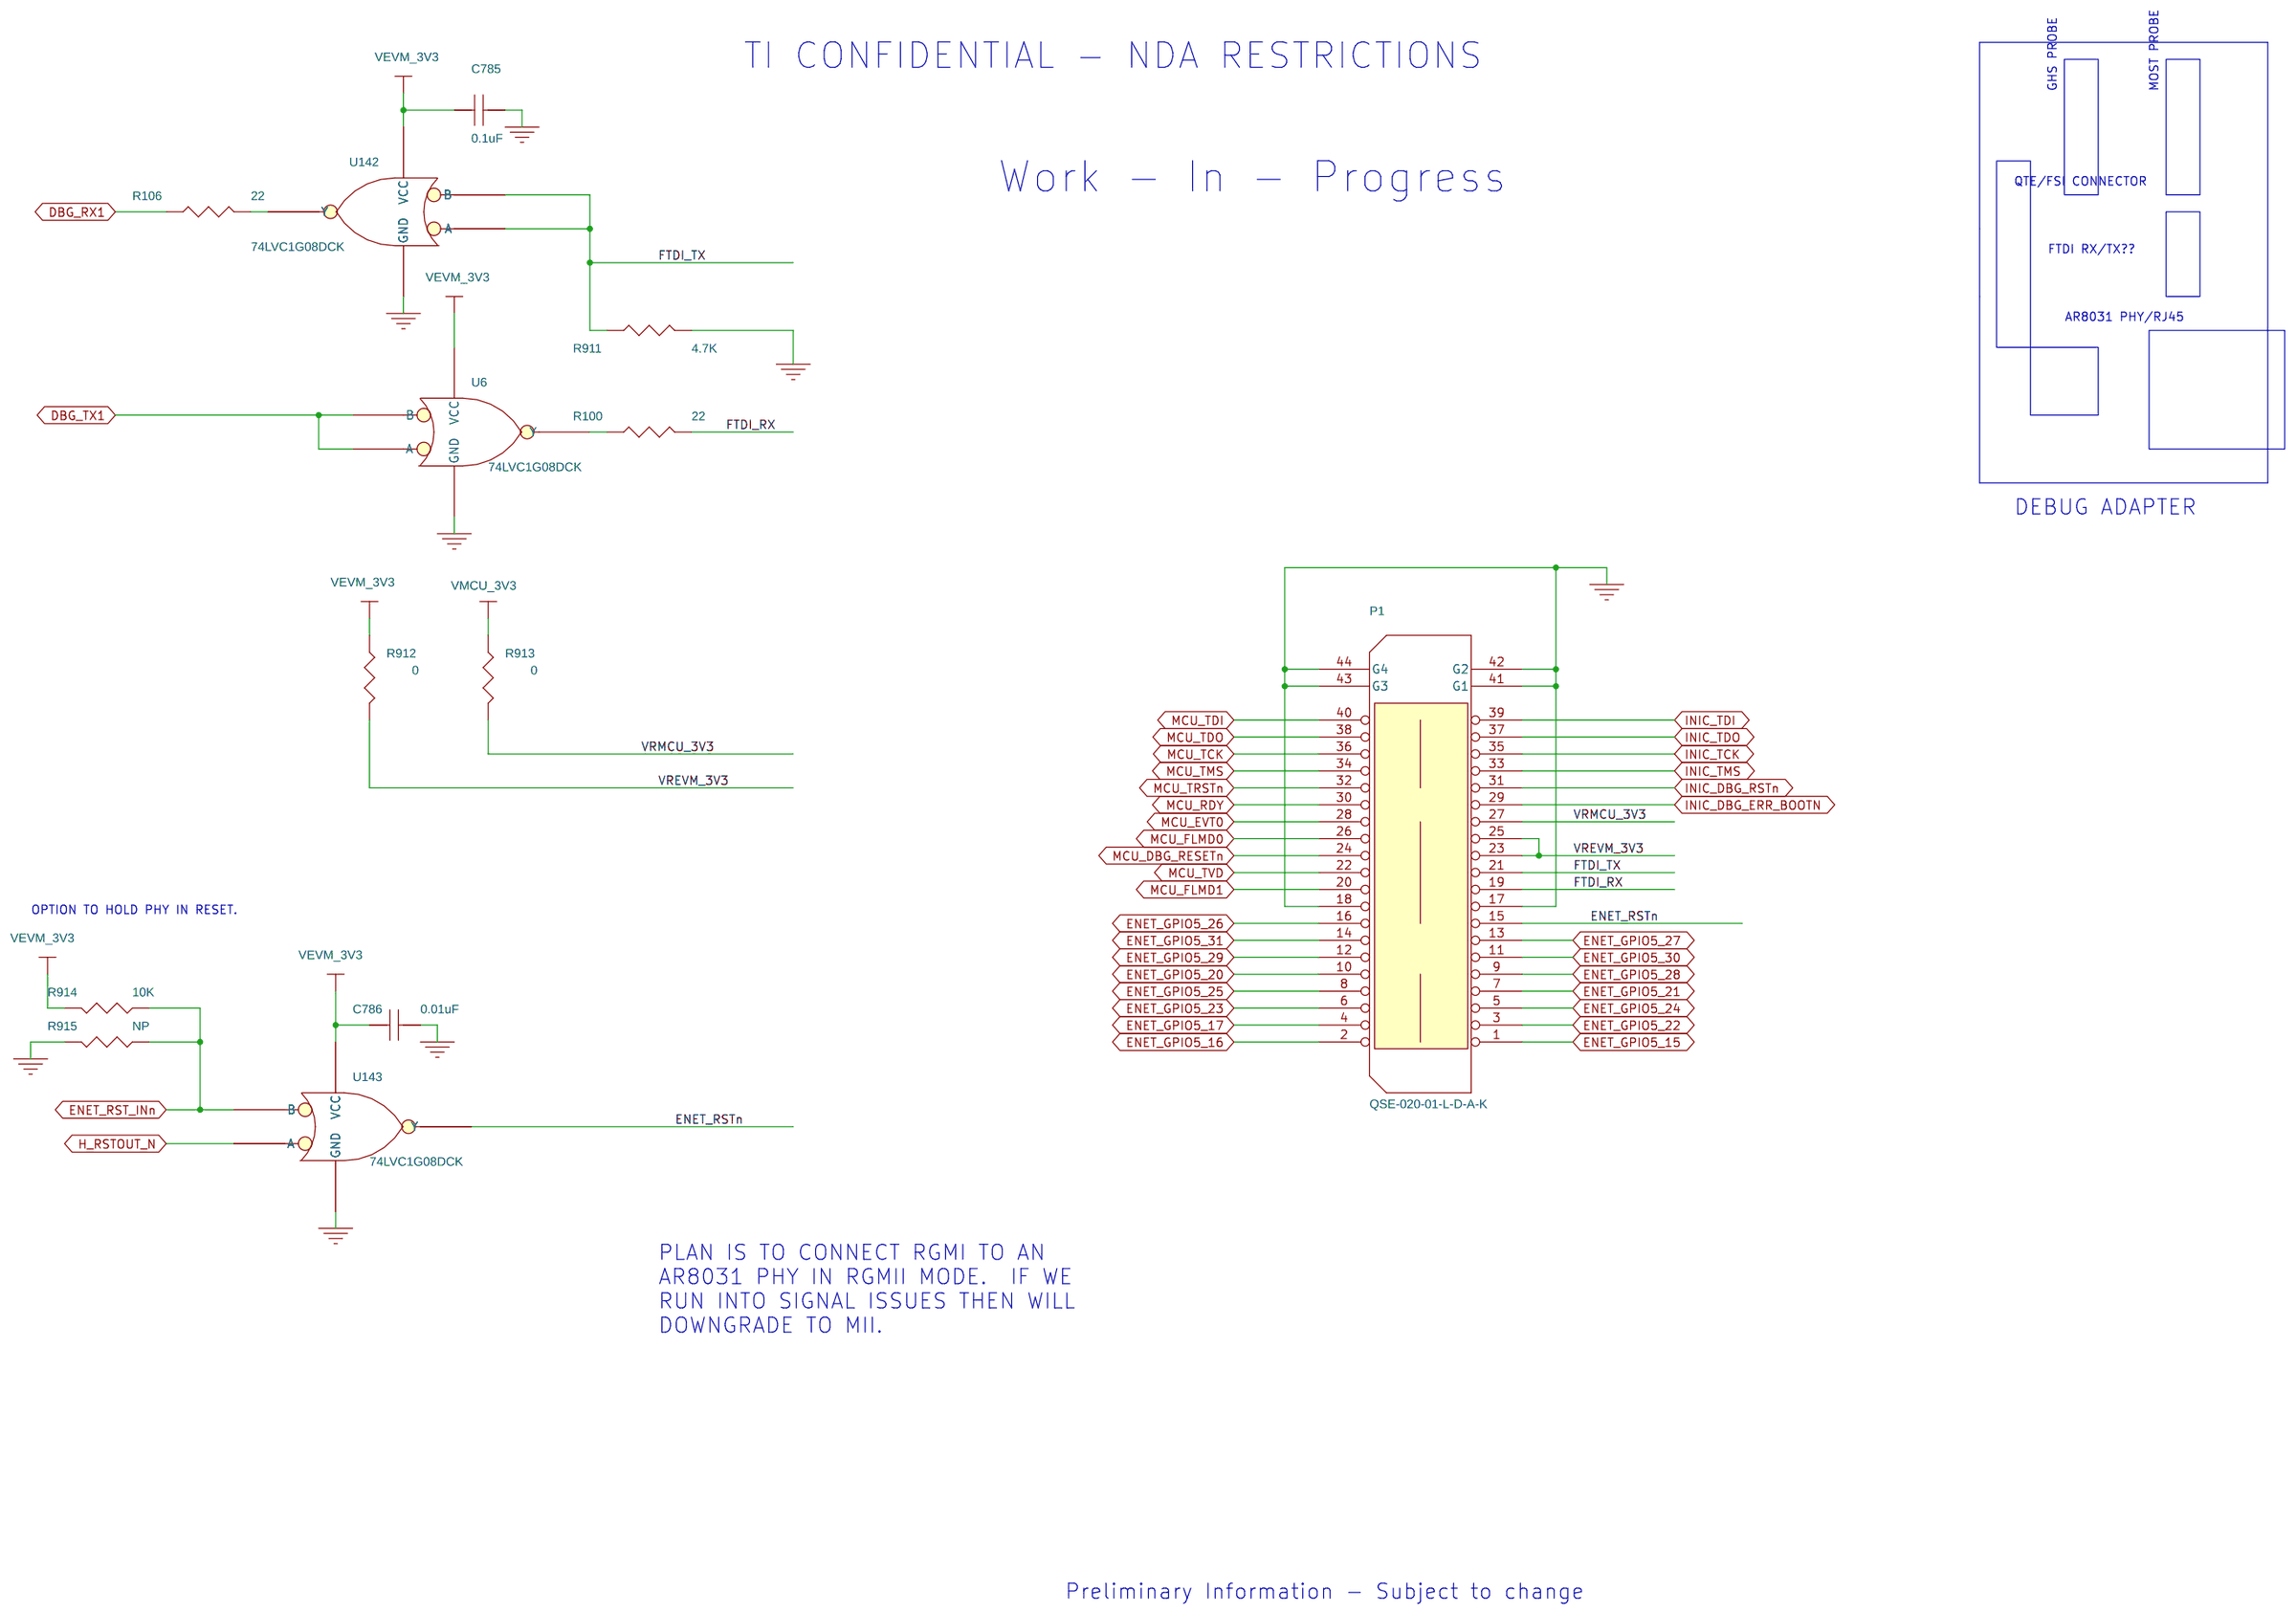
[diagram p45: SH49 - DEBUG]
47 SH50 - BD POWER INPUT: size B; rev: A
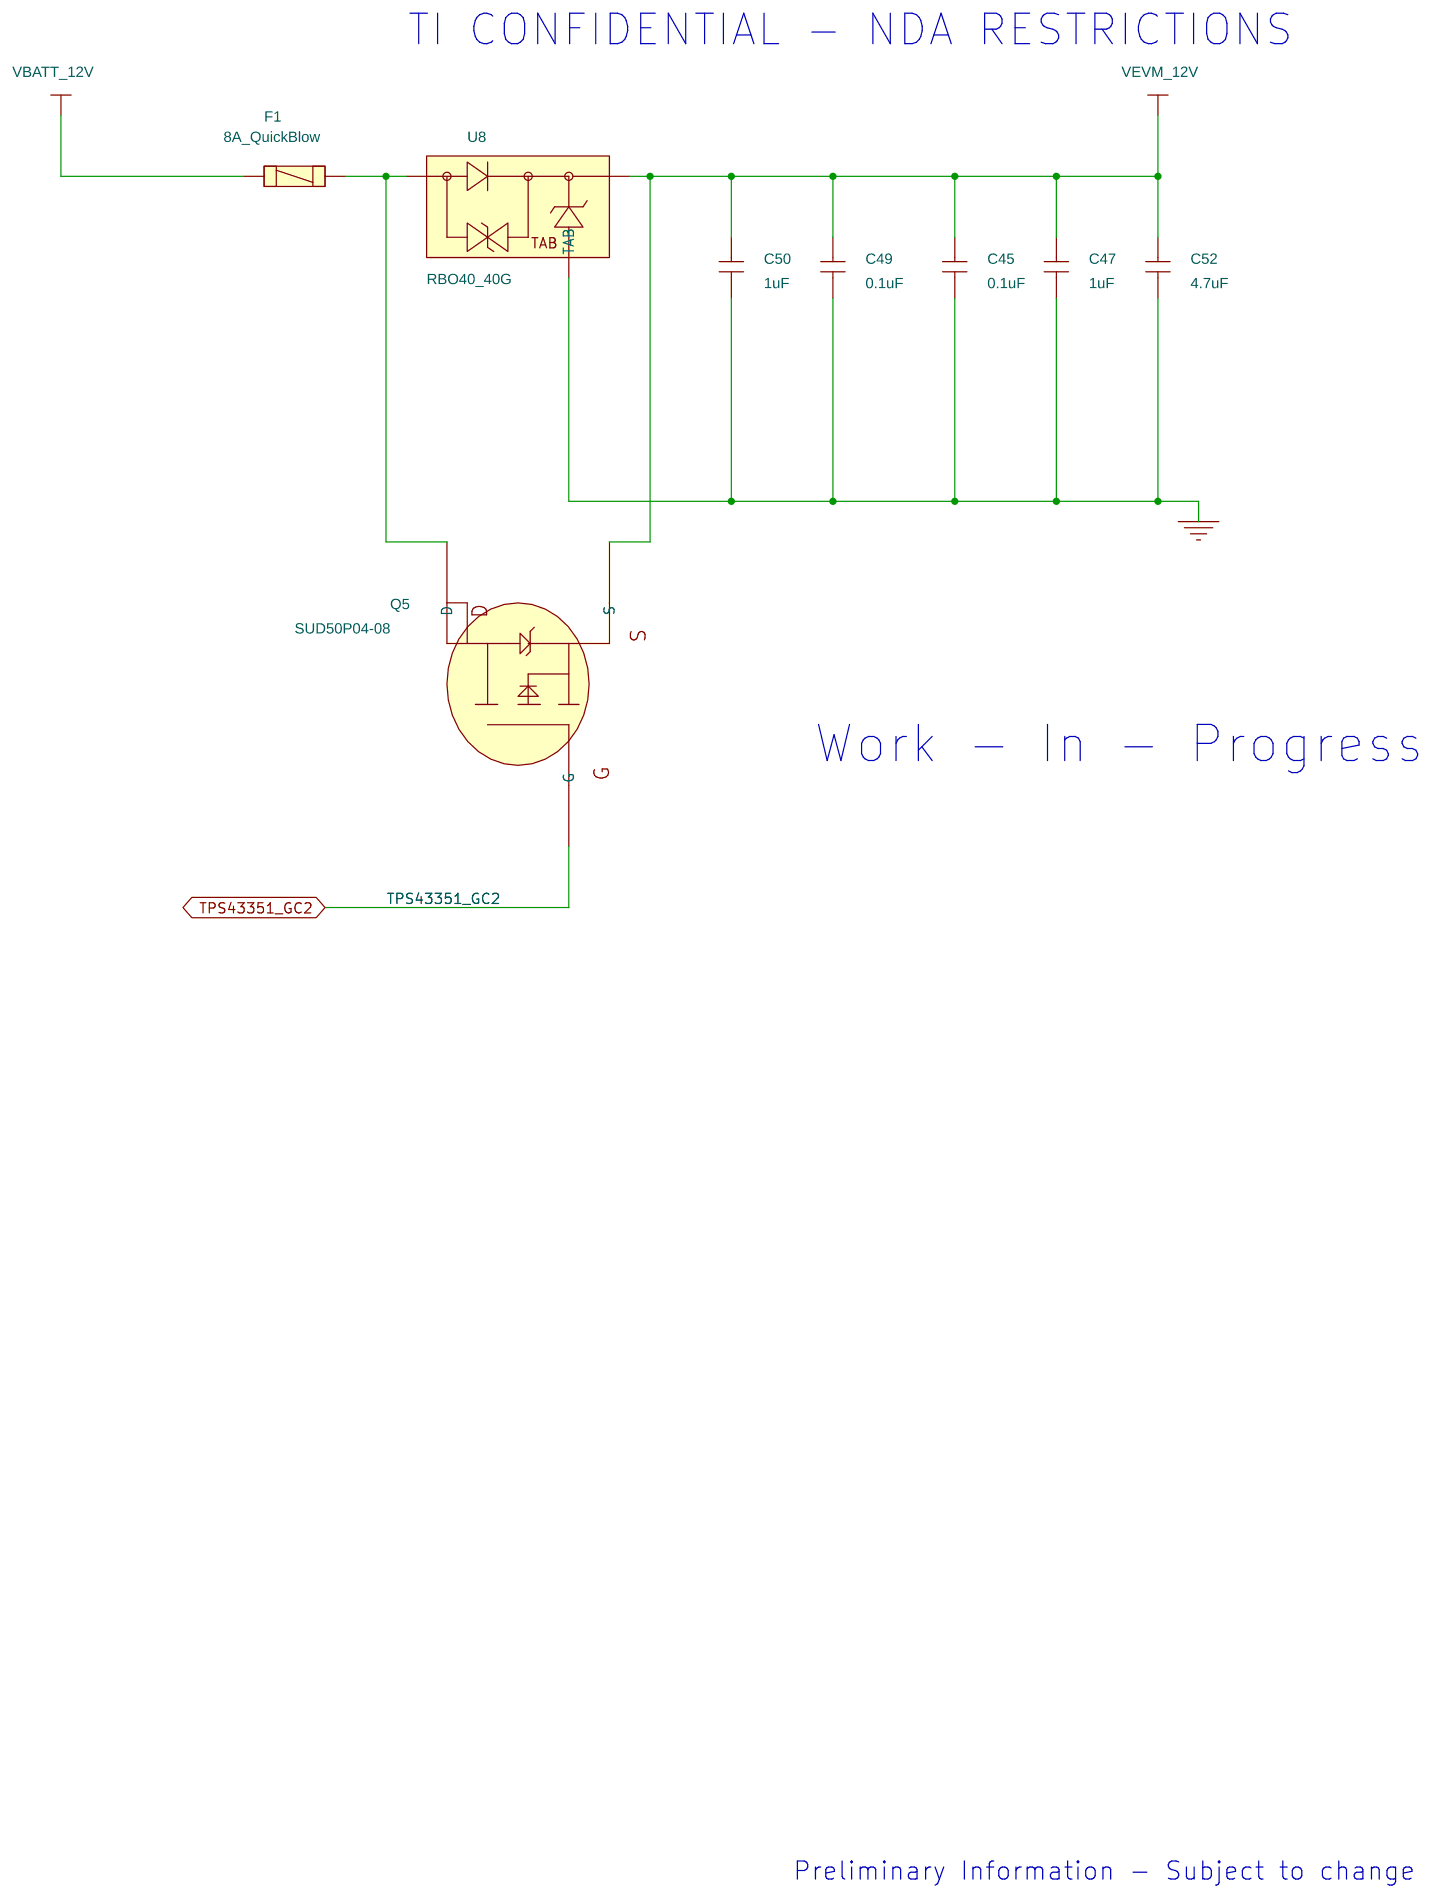
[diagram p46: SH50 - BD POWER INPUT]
48 SH51 - BD POWER PRIM CNVTR: size B; rev: A
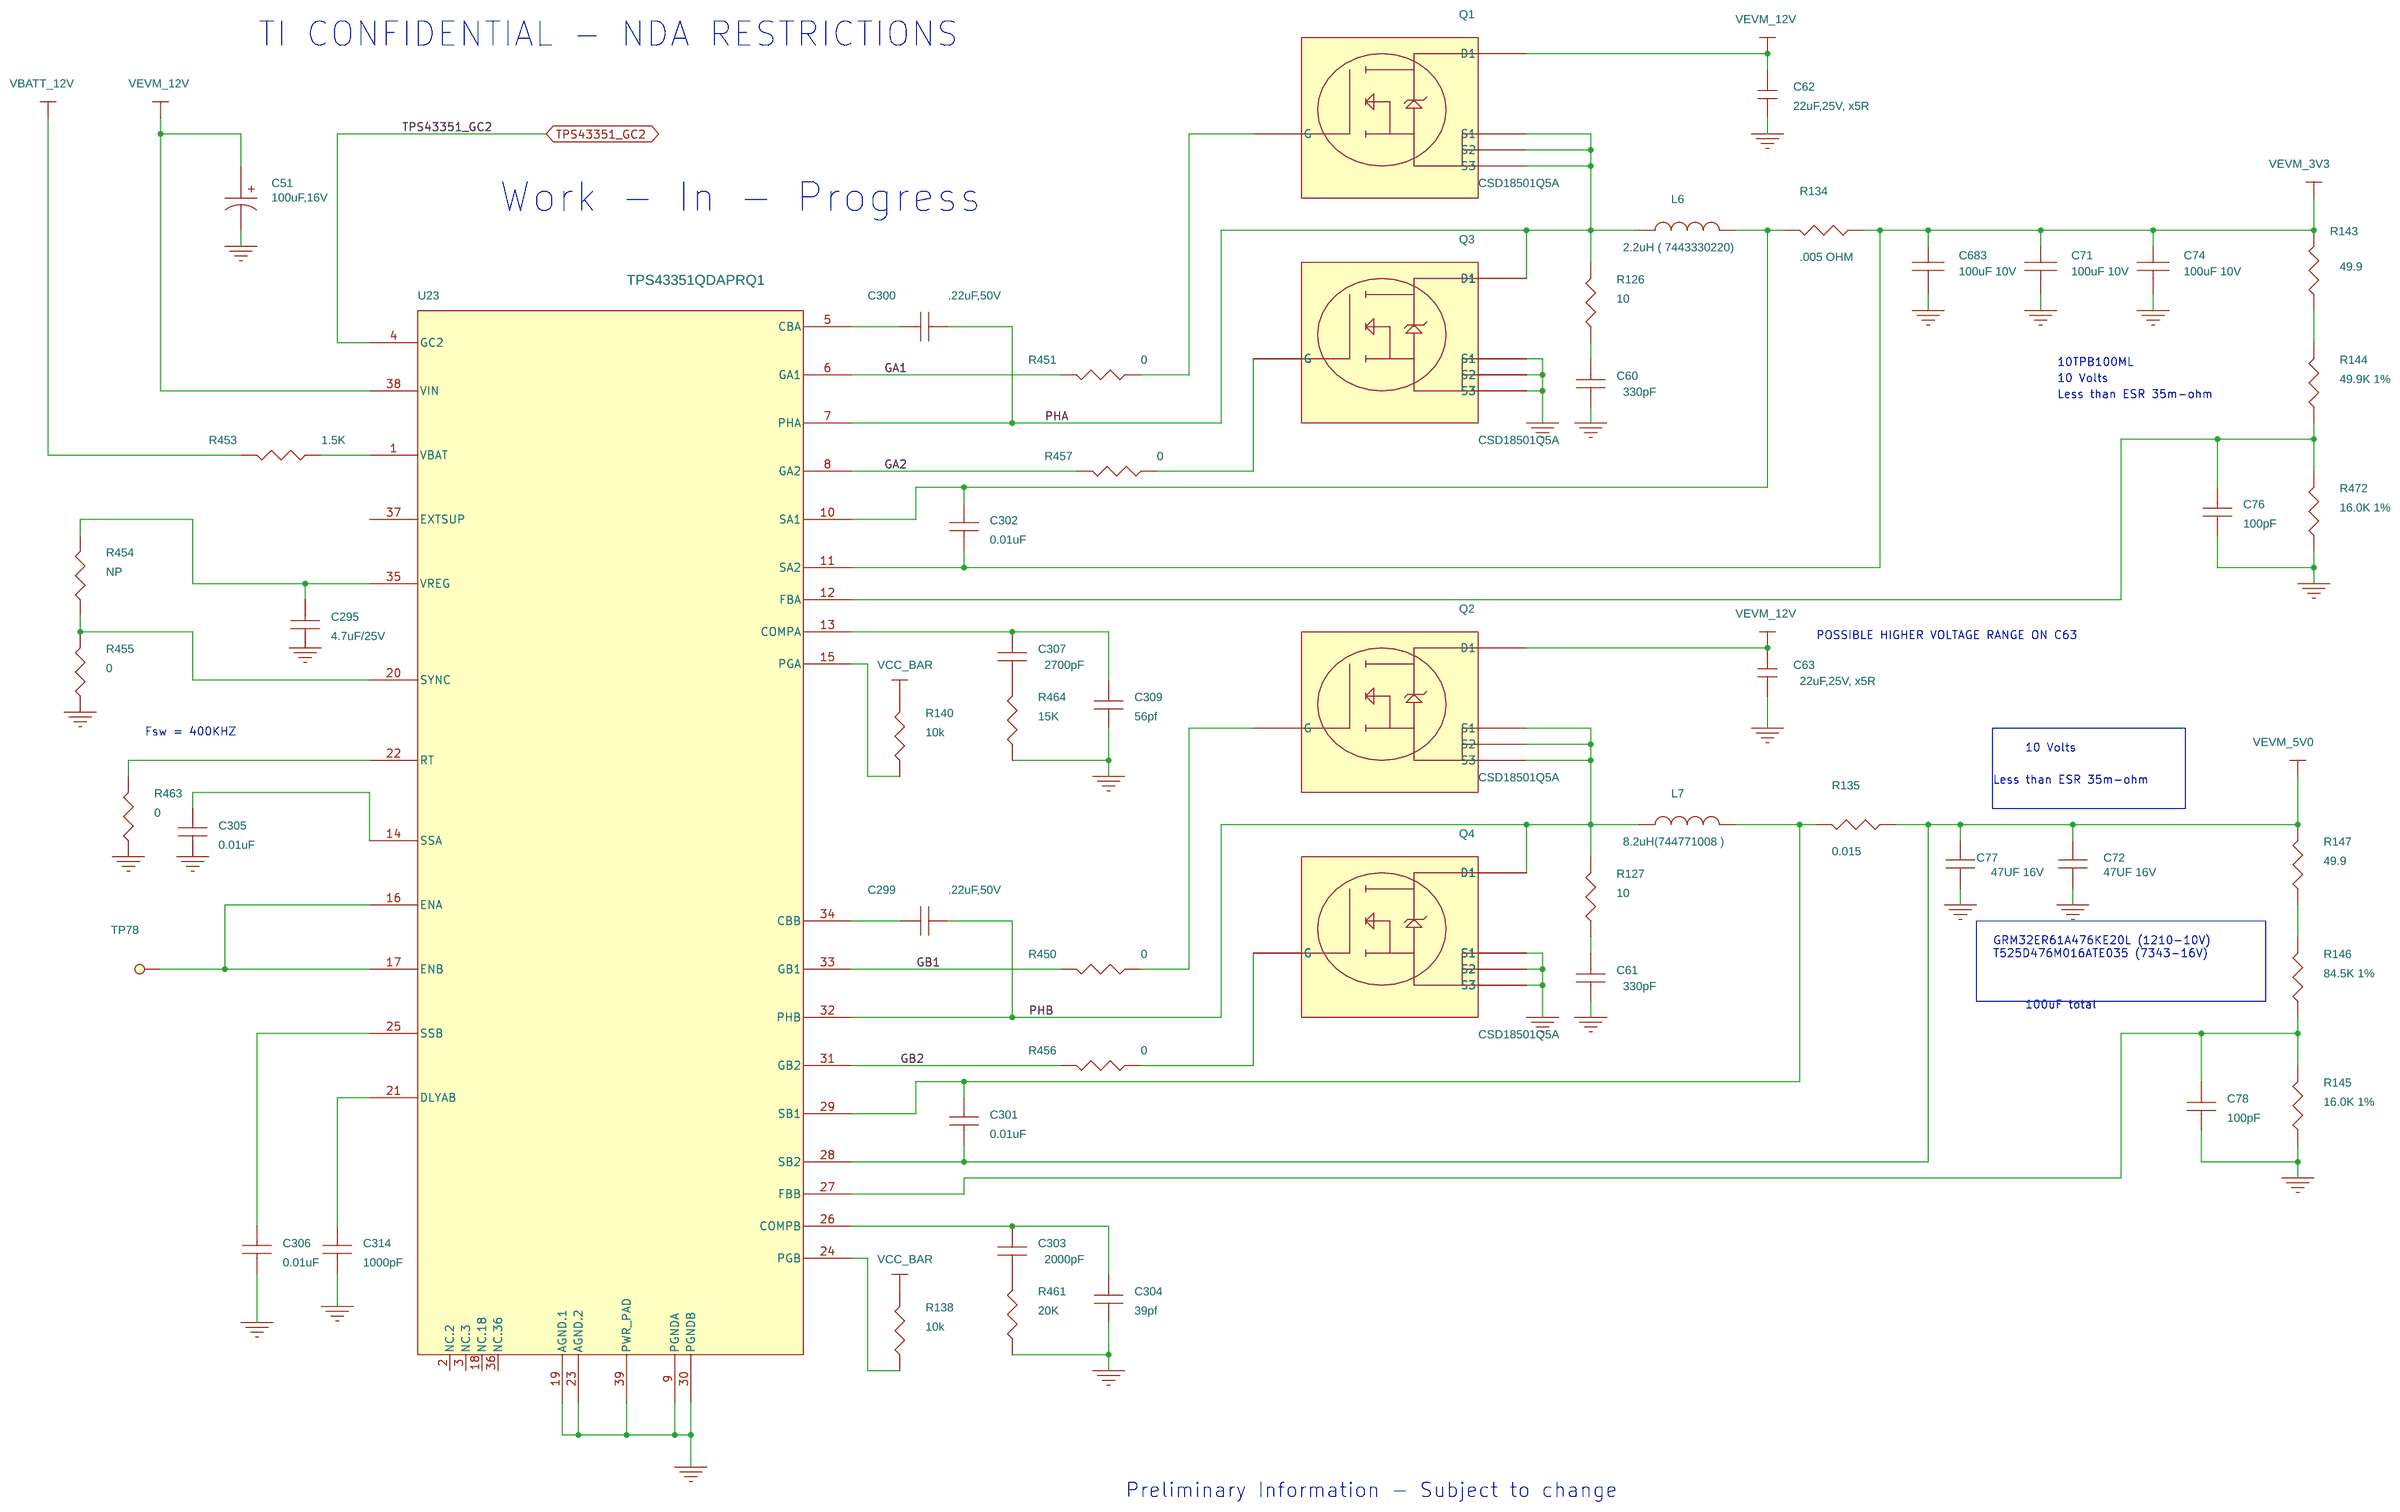
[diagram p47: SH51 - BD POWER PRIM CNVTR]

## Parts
sheet SH40 - VIDEO OUT FPD LINK
C5  0.1uF  [c402-25]
C6  0.1uF  [c402-25]
C7  4.7uF  [c603-35x45]
C8  4.7uF  [c603-35x45]
C13  4.7uF  [c603-35x45]
C228  4.7uF  [c603-35x45]
C229  4.7uF  [c603-35x45]
C231  0.1uF  [c402-25]
C232  0.1uF  [c402-25]
C234  4.7uF  [c603-35x45]
C235  4.7uF  [c603-35x45]
C236  0.1uF  [c402-25]
C717  0.1uF  [c402-25]
C718  0.1uF  [c402-25]
C719  0.1uF  [c402-25]
FL9  DLW21SN121HQ2  [EMI-36X15-DLW21]
L2  NP  [l603-35x45]
L3  Ferrite Chip  [l603-35x45]
R8  10K  [r402-25]
R9  10K  [r402-25]
R10  10K  [r402-25]
R11  10K  [r402-25]
R20  10K  [r402-25]
R22  NP  [r402-25]
R332  10K  [r402-25]
R333  NP  [r402-25]
R338  NP  [r402-25]
R838  10K  [r402-25]
R839  NP  [r402-25]
R840  NP  [r402-25]
R841  NP  [r402-25]
R842  0  [r402-25]
R843  0  [r402-25]
R844  0  [r402-25]
R845  0  [r402-25]
R846  0  [r402-25]
U3  DS90UR905QSQE/NOPB  [QFN48-11X35]
sheet SH41 - VIDEO IN
C715  680pF  [c402-25]
C788  0.1uF  [c402-25]
C789  1uF  [c402-25]
C790  1uF  [c402-25]
C791  1uF  [c402-25]
C792  0.1uF  [c402-25]
C793  0.1uF  [c402-25]
C794  2.2uF  [c402-25]
C795  330pF  [c603-35x45]
C796  330pF  [c603-35x45]
C797  0.1uF  [c402-25]
C798  33pF  [c402-25]
C799  33pF  [c402-25]
C800  0.1uF  [c402-25]
C801  0.1uF  [c402-25]
L23  Ferrite Chip  [l603-35x45]
L24  2.7uH  [L603-35x45]
L25  2.7uH  [L603-35x45]
R943  226  [r603-35x45]
R944  10K  [r402-25]
R945  10K  [r402-25]
R946  NP  [r402-25]
R947  22  [r402-25]
R948  22  [r402-25]
R949  22  [r402-25]
R950  22  [r402-25]
R951  56  [r603-35x45]
R952  0  [r402-25]
R953  226  [r603-35x45]
R954  75  [r603-35x45]
R955  0  [r402-25]
R956  100K  [r402-25]
R957  22  [r402-25]
R958  10K  [r402-25]
R959  NP  [r402-25]
RN32  RPACK4-10  [rpak8-10x25-28v]
RN33  RPACK4-10  [rpak8-10x25-28v]
U132  TVP5150AM1  [pbs32-12x57]
Y7  14.31818MHz  [xtal2-75x94]
sheet SH42 - AUDIO CO-DEC
C130  10uF  [c1206-40x70-POL]
C131  0.1uF  [c402-25]
C132  0.1uF  [c402-25]
C133  4.7uF  [c603-35x45]
C134  0.1uF  [c402-25]
C141  0.1uF  [c402-25]
C142  0.1uF  [c402-25]
C144  10uF  [c1206-40x70-POL]
C151  0.1uF  [c402-25]
C152  10uF  [c1206-40x70-POL]
C153  0.1uF  [c402-25]
C168  2.2uF  [c603-35x45]
C173  0.1uF  [c402-25]
C536  1uF  [c402-25]
C558  0.1uF  [c402-25]
C565  0.1uF  [c402-25]
C566  0.1uF  [c402-25]
C567  0.1uF  [c402-25]
C568  0.1uF  [c402-25]
C575  NP  [c402-25]
C647  2.2uF  [c603-35x45]
C648  0.1uF  [c402-25]
L19  BLM21PG221SN1D  [l805-35x60]
L21  BLM21PG221SN1D  [l805-35x60]
L22  BLM21PG221SN1D  [l805-35x60]
P12  Line Out  [st_3500]
R249  NP  [r402-25]
R250  10  [r402-25]
R251  10  [r402-25]
R252  10  [r402-25]
R253  10  [r402-25]
R254  22  [r402-25]
R257  2.2K  [r402-25]
R260  2.2K  [r402-25]
R262  NP  [r402-25]
R266  NP  [r402-25]
R281  100  [r402-25]
R287  20K  [r402-25]
R642  20K  [r402-25]
R643  20K  [r402-25]
R644  2.2K  [r402-25]
R654  NP  [r402-25]
R659  NP  [r402-25]
R664  NP  [r402-25]
R668  NP  [r402-25]
R671  0  [r402-25]
R672  2.2K  [r402-25]
R673  330  [r402-25]
R675  NP  [r402-25]
R697  100  [r402-25]
R702  20K  [r402-25]
R800  NP  [r402-25]
R801  0  [r402-25]
R802  NP  [r402-25]
U55  TPS77018DBVT  [dbv5-27x39]
U59  TLV320AIC3106  [rgz48-11x34]
sheet SH43 - PMIC CONTROL
C100  0.1uF  [c402-25]
C115  12pF/0402/50V  [c402-25]
C116  12pF/0402/50V  [c402-25]
C403  2.2uF/0402/6.3V  [c402-25]
C435  0.1uF  [c402-25]
C696  0.1uF  [c402-25]
R191  NP  [r402-25]
R194  NP  [r201-6p6spc]
R205  10K  [r201-6p6spc]
R206  NP  [r201-6p6spc]
R207  0  [r201-6p6spc]
R208  NP  [r201-6p6spc]
R209  NP  [r201-6p6spc]
R210  10K  [r201-6p6spc]
R211  1.2K  [r201-6p6spc]
R483  NP  [r201-6p6spc]
R513  10K  [r402-25]
R514  NP  [r402-25]
R516  10K  [r201-6p6spc]
R518  10K  [r402-25]
R533  NP  [r201-6p6spc]
R534  10K  [r201-6p6spc]
R535  10K  [r201-6p6spc]
R537  NP  [r201-6p6spc]
R549  0  [r201-6p6spc]
R565  10K  [r201-6p6spc]
R567  NP  [r402-25]
R570  NP  [r201-6p6spc]
R588  2.2K  [r402-25]
R589  NP  [r201-6p6spc]
R590  10K  [r201-6p6spc]
R592  NP  [r201-6p6spc]
R708  NP  [r201-6p6spc]
R709  NP  [r201-6p6spc]
R782  0  [r402-25]
R783  NP  [r402-25]
R784  NP  [r402-25]
R785  NP  [r402-25]
TP24  NP  [tp20]
TP30  NP  [tp20]
TP31  NP  [tp20]
TP32  NP  [tp20]
TP41  NP  [tp20]
TP43  NP  [tp20]
U101  SN74AVC2T45DCT  [dct8-14x70]
Y4  Crystal_CM519_CTS407  [xtal2-cm519-dual-cts407]
sheet SH44 - PMIC LDOS
C99  2.2uF/0402/6.3V  [c402-25]
C101  2.2uF/0402/6.3V  [c402-25]
C102  2.2uF/0402/6.3V  [c402-25]
C103  2.2uF/0402/6.3V  [c402-25]
C346  2.2uF/0402/6.3V  [c402-25]
C352  2.2uF/0402/6.3V  [c402-25]
C381  2.2uF/0402/6.3V  [c402-25]
C407  2.2uF/0402/6.3V  [c402-25]
C408  2.2uF/0402/6.3V  [c402-25]
C430  2.2uF/0402/6.3V  [c402-25]
C431  2.2uF/0402/6.3V  [c402-25]
C433  2.2uF/0402/6.3V  [c402-25]
C459  10uF/6.3V  [c603-35x45]
C680  2.2uF/0402/6.3V  [c402-25]
sheet SH45 - PMIC SMPS1-5
C349  47uF/10V  [C1210-70x102]
C350  47uF/10V  [C1210-70x102]
C353  4.7uF 10V  [C805-35X60]
C354  4.7uF 10V  [C805-35X60]
C375  4.7uF 10V  [C805-35X60]
C376  4.7uF 10V  [C805-35X60]
C377  47uF/10V  [C1210-70x102]
C378  47uF/10V  [C1210-70x102]
C379  4.7uF 10V  [C805-35X60]
C410  47uF/10V  [C1210-70x102]
L13  1uH  [ind2-65x90-ihlp1616]
L14  1uH  [ind2-65x90-ihlp1616]
L15  1uH  [ind2-65x90-ihlp1616]
L16  1uH  [ind2-65x90-ihlp1616]
L17  1uH  [ind2-65x90-ihlp1616]
sheet SH46 - PMIC SMPS6-9 INT POWER
C326  47uF/10V  [C1210-70x102]
C327  47uF/10V  [C1210-70x102]
C328  47uF/10V  [C1210-70x102]
C338  4.7uF 10V  [C805-35X60]
C341  4.7uF 10V  [C805-35X60]
C342  4.7uF 10V  [C805-35X60]
C380  4.7uF 10V  [C805-35X60]
C409  47uF/10V  [C1210-70x102]
C432  4.7uF 10V  [C805-35X60]
C434  0.1uF  [c402-25]
C810  4.7uF 10V  [C805-35X60]
E10  NFM21PC474R1C3D  [emi-NFM21p]
L9  1uH  [ind2-65x90-ihlp1616]
L10  1uH  [ind2-65x90-ihlp1616]
L11  1uH  [ind2-65x90-ihlp1616]
L18  1uH  [ind2-65x90-ihlp1616]
R192  0  [r402-25]
R193  0  [r402-25]
R591  0  [r201-6p6spc]
TP42  NP  [tp20]
U45  TPS659039  [zws169-13p8]  (sections A,B,C,D,E,F)
sheet SH47 - RESET GENERATION
C329  NP  [c402-25]
C330  0.1uF  [c402-25]
C348  NP  [c402-25]
C358  0.1uF  [c402-25]
C421  220pF 50V  [c603-35x45]
C441  0.1uF  [c402-25]
R151  0  [r402-25]
R152  10K  [r402-25]
R153  10K  [r402-25]
R529  10K  [r402-25]
R530  10K  [r402-25]
R531  0  [r402-25]
R554  0  [r402-25]
R555  NP  [r402-25]
R583  10K  [r402-25]
R596  10K  [r402-25]
R623  10K  [r402-25]
R940  0  [r402-25]
SW4  PB_SW  [SW4-7914G]
U37  TPS3808G09DBVR  [DBV6-27X39-6]
U44  TPS3808G09DBVR  [DBV6-27X39-6]
U102  TPS3808G09DBVR  [DBV6-27X39-6]
sheet SH48 - SOC BOOT SETTINGS
J21  HEADER 2  [jump1x2-5635-2mm]
J24  HEADER 2  [jump1x2-5635-2mm]
R80  NP  [r201-6p6spc]
R81  NP  [r201-6p6spc]
R82  NP  [r201-6p6spc]
R83  1K  [r201-6p6spc]
R84  NP  [r201-6p6spc]
R85  1K  [r201-6p6spc]
R86  10K  [r201-6p6spc]
R87  10K  [r201-6p6spc]
R88  10K  [r201-6p6spc]
R89  NP  [r201-6p6spc]
R90  NP  [r201-6p6spc]
R91  NP  [r201-6p6spc]
R92  NP  [r201-6p6spc]
R93  NP  [r201-6p6spc]
R94  NP  [r201-6p6spc]
R95  10K  [r201-6p6spc]
R110  10K  [r201-6p6spc]
R111  10K  [r201-6p6spc]
R112  10K  [r201-6p6spc]
R113  10K  [r201-6p6spc]
R114  10K  [r201-6p6spc]
R115  10K  [r201-6p6spc]
R116  NP  [r201-6p6spc]
R117  NP  [r201-6p6spc]
R118  NP  [r201-6p6spc]
R119  10K  [r201-6p6spc]
R120  10K  [r201-6p6spc]
R121  10K  [r201-6p6spc]
R122  10K  [r201-6p6spc]
R123  10K  [r201-6p6spc]
R124  10K  [r201-6p6spc]
R125  NP  [r201-6p6spc]
R569  NP  [r201-6p6spc]
R599  NP  [r201-6p6spc]
R757  10K  [r201-6p6spc]
R766  10K  [r201-6p6spc]
sheet SH49 - DEBUG
C785  0.1uF  [c402-25]
C786  0.01uF  [c402-25]
P1  QSE-020-01-L-D-A-K  [QSE_020]
R100  22  [r402-25]
R106  22  [r402-25]
R911  4.7K  [r402-25]
R912  0  [r402-25]
R913  0  [r402-25]
R914  10K  [r201-6p6spc]
R915  NP  [r201-6p6spc]
U6  74LVC1G08DCK  [dck-5]
U142  74LVC1G08DCK  [dck-5]
U143  74LVC1G08DCK  [dck-5]
sheet SH50 - BD POWER INPUT
C45  0.1uF  [c603-35x45]
C47  1uF  [c805-35x60]
C49  0.1uF  [c603-35x45]
C50  1uF  [c805-35x60]
C52  4.7uF  [c1210-70x102]
F1  8A_QuickBlow  [FUSEFOLDER-OMNI-BLOK]
Q5  SUD50P04-08  [to-252-D-PAK]
U8  RBO40_40G  [dpak3-55x120-4]
sheet SH51 - BD POWER PRIM CNVTR
C51  100uF,16V  [c7343-84x118]
C60  330pF  [c603-35x45]
C61  330pF  [c603-35x45]
C62  22uF,25V, x5R  [c1210-70x102]
C63  22uF,25V, x5R  [c1210-70x102]
C71  100uF 10V  [c7343-84x118]
C72  47UF 16V  [c1210-c7343-dual]
C74  100uF 10V  [c7343-84x118]
C76  100pF  [c402-25]
C77  47UF 16V  [c1210-c7343-dual]
C78  100pF  [c402-25]
C295  4.7uF/25V  [c805-35x60]
C299  .22uF,50V  [c603-35x45]
C300  .22uF,50V  [c603-35x45]
C301  0.01uF  [c402-25]
C302  0.01uF  [c402-25]
C303  2000pF  [c402-25]
C304  39pf  [c402-25]
C305  0.01uF  [c402-25]
C306  0.01uF  [c402-25]
C307  2700pF  [c402-25]
C309  56pf  [c402-25]
C314  1000pF  [c402-25]
C683  100uF 10V  [c7343-84x118]
L6  2.2uH ( 7443330220)  [choke-power-we-hcc]
L7  8.2uH(744771008 )  [ind2-115x213-12mm]
Q1  CSD18501Q5A  [pwr-q5a-slps319]
Q2  CSD18501Q5A  [pwr-q5a-slps319]
Q3  CSD18501Q5A  [pwr-q5a-slps319]
Q4  CSD18501Q5A  [pwr-q5a-slps319]
R126  10  [r603-35X45]
R127  10  [r603-35X45]
R134  .005 OHM  [r2725-125x250]
R135  0.015  [R2512]
R138  10k  [r402-25]
R140  10k  [r402-25]
R143  49.9  [r603-35x45]
R144  49.9K 1%  [r402-25]
R145  16.0K 1%  [r603-35x45]
R146  84.5K 1%  [r603-35x45]
R147  49.9  [r603-35x45]
R450  0  [r402-25]
R451  0  [r402-25]
R453  1.5K  [r603-35x45]
R454  NP  [r402-25]
R455  0  [r402-25]
R456  0  [r402-25]
R457  0  [r402-25]
R461  20K  [r402-25]
R463  0  [r402-25]
R464  15K  [r402-25]
R472  16.0K 1%  [r603-35x45]
TP78  NP  [tp20]
U23  TPS43351QDAPRQ1  [dap38]

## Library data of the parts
C5 C6 C231 C232 C236 C330 C358 C717-C719 C785 C792 C793 C797 C800 C801 = CAP: Part #: 101587-1100R
C7 C8 C13 C228 C229 C234 C235 = CAP: Part #: 102590-0470R
FL9 = DLW21SN121HQ2: Part #: 104184-1201R
L2 = FERRITE_CHIP_0: Part #: l0603-nopop
L3 L23 = FERRITE_CHIP_0: Part #: 101858-2201R
R8-R11 R20 R152 R153 R332 R529 R530 R838 R944 R945 R958 = R: Part #: 101370-1003R
R22 R333 R338 R567 R839-R841 = R: Part #: R0402-NOPOP
R151 R531 R554 R842-R846 R912 R913 R940 = R: Part #: 101370-0001R
U3 = DS90UH925Q_1: Part #: 104396-0001R
C715 = 0_1.1uF_Chip_Cap: Part #: 101587-6803R
C788 = 0_1.1uF_Chip_Cap: Part #: 101587-1100R
C789-C791 = CAP_NP: Part #: 102962-0100R
C794 = CAP: Part #: 103649-0220R
C795 C796 = 0_1.1uF_Chip_Cap: Part #: 100993-3303R
C798 C799 = CAP_NP_3: Part #: 101782-1334R
L24 L25 = INDUCTOR_0: Part #: 101919-0270R
R943 R953 = R_805: Part #: 100642-2261R
R946 R959 = R: Part #: r0402-nopop
R100 R106 R947-R950 R957 = R: Part #: 101370-2200R
R951 = R_805: Part #: 100642-5600R
R952 R955 = R_805: Part #: 101370-0001R
R954 = R_805: Part #: 100642-7500R
R956 = R_10K_0402_1%_Multi: Part #: 101370-1004R
RN32 RN33 = R-PACK4: Part #: 101327-1000R
U132 = TVP5150AM1: Part #: 101915-0001R
Y7 = CRYSTAL_0_v2: Part #: 101590-0143R
C130 C144 C152 = CAPACITOR_POL_0: Part #: 101003-0101R
C131 C132 C134 C141 C142 C151 C153 C173 C558 C565-C568 C648 = CAP_NP: Part #: 101587-1100R
C133 = CAP_NP_2: Part #: 102590-0470R
C168 C647 = CAP: Part #: 102965-0220R
C536 = C_0: Part #: 102962-0100R
C575 = CAP_NP: Part #: C0402-NOPOP
L19 L21 L22 = INDUCTOR: Part #: 101228-2201R
P12 = Kycon_ST-3500_0: Part #: 101012-0001R
R249 R262 R266 R654 R659 R664 R668 R675 = R_0: Part #: R0402-NOPOP
R250-R253 = R_0: Part #: 101370-1000R
R254 = RESISTOR: Part #: 101370-2200R
R257 R260 R644 R672 = R_0: Part #: 101370-2202R
R281 R697 = R: Part #: 101370-1001R
R287 R642 R643 R702 = R_0: Part #: 101370-2003R
R671 R801 = R_0: Part #: 101370-0001R
R673 = R_0: Part #: 101370-3301R
R800 R802 = R_0: Part #: r0402-nopop
U55 = TPS76901_1: Part #: 101320-0018R
U59 = TLV320AIC3106_0: Part #: 102800-0001R
C100 C434 = C_100nF_0402_6.3V_X5R_0402: Part #: 101587-1100R
C115 C116 = C_12pF_0402_50V_COG_0402: Part #: 101782-1124R
C99 C101-C103 C346 C352 C381 C403 C407 C408 C430 C431 C433 = C_2.2uF_0402_6.3V_X5R_0402: Part #: 103649-0220R
C435 C696 = CAP_NP: Part #: 101587-1100R; Spectrum Part#: 100994-1100
R191 R514 R783-R785 = R_10K_0402_1%_Multi: Part #: R0402-NOPOP
R194 R206 R208 R209 R483 R533 R537 R570 R589 R592 = R_10K_0402_1%_Multi: Part #: R0201-NOPOP
R205 R210 R516 R534 R535 R565 R590 = R_10K_0402_1%_Multi: Part #: 103158-1003R
R207 R549 R591 = R_10K_0402_1%_Multi: Part #: 103158-0001R
R211 = R_10K_0402_1%_Multi: Part #: 103158-1202R
R513 R518 = R_10K_0402_1%_Multi: Part #: 101370-1003R
R588 = R_10K_0402_1%_Multi: Part #: 101370-2202R
R708 R709 R915 = R: Part #: R0201-NOPOP
R782 = R_10K_0402_1%_Multi: Part #: 101370-0001R
TP24 TP30-TP32 TP41-TP43 = TP_0: Part #: SMT-TP020
U101 = SN74AVC2T45DCT: Part #: 102051-0001R
Y4 = Crystal_CM519_CTS407: Part #: 104248-1638R
C459 = C_10uF_6.3V_X5R_0603: Distributor ref: 1288201; Part #: 102963-0101R
C680 = CAP_NP_0: Part #: 103649-0220R
C326-C328 C349 C350 C377 C378 C409 C410 = C_10uF_6.3V_X5R_0603: Distributor ref: 1288201; Part #: 103055-0471R
C338 C341 C342 C353 C354 C375 C376 C379 C380 = C_4.7uF_0402_6.3V_X5R_0402: Part #: 101063-0470R
L13 L15 L17 = IND_1.47uH_DFE252012C_R47N: Manufacturer ref: IHLP-1616ABER1R0M11; Part #: 104246-0100R
L11 L14 L16 L18 = IND_0.47uH_DFE252010C_R47N: Manufacturer ref: IHLP-1616ABER1R0M11; Part #: 104246-0100R
C432 C810 = C_2.2uF_0402_6.3V_X5R_0402: Part #: 101063-0470R
E10 = NFM_1: Part #: 102569-1470R
L9 L10 = IND_0.47uH_LQM2MPR47NG0: Manufacturer ref: IHLP-1616ABER1R0M11; Part #: 104246-0100R
R192 R193 = R_0_0402_1%_Multi: Part #: 101370-0001R
U45 = TPS659038_2: Part #: 104252-0003R-TI
C329 C348 = CAP: Part #: C0402-NOPOP
C421 = CAP_NP_2: Part #: 100993-1223R
C441 = CAP_NP_2: Part #: 101587-1100R
R555 = R_2: Part #: R0402-NOPOP
R138 R140 R583 = RESISTOR: Part #: 101370-1003R
R596 R623 = R_2: Part #: 101370-1003R
SW4 = SW_PUSHBUTTON_3: Part #: 101023-0001R
U37 U44 U102 = TPS3808G09DBVR_0: Part #: 102020-0009R
J21 J24 = HEADER_2: Part #: 100546-0002R
R80-R82 R84 R89-R94 R116-R118 R125 R569 R599 = R_1: Part #: r0201-nopop
R83 R85 = R_1: Part #: 103158-1002R
R86-R88 R95 R110-R115 R119-R124 = R_1: Part #: 103158-1003R
R757 R766 R914 = R: Part #: 103158-1003R
C301 C302 C305 C306 C786 = CAP: Part #: 101587-1101R
P1 = J_-_SamTec_QSH020_40pin_2: Part #: 101881-0020R
R911 = R: Part #: 101370-4702R
U6 U142 U143 = 1G08: Part #: 101057-0008R
C45 C49 = CAP_NP: Part #: 100993-1100R
C47 C50 = CAP_NP: Part #: 100201-0100R
C52 = CAP_NP: Part #: 103058-0470R
F1 = NANO-SMF_0: Part #: 102110-0008R
Q5 = SUD50P04-08: Part #: 103998-0001R
U8 = RBO40_1: Part #: 103038-0001R
C51 = CAP_POL: Part #: 101290-0102R
C60 C61 = CAP: Part #: 100993-3303R
C62 C63 = CAP_NP: Part #: 104292-0221R
C71 C74 C683 = C_0: Part #: 104290-0102R
C72 C77 = CAP: Part #: 104294-0471R
C76 C78 = CAP: Part #: 101782-1103R
C295 = CAP: Part #: 103751-0470R
C299 C300 = CAP: Part #: 103885-1220R
C303 = CAP: Part #: 104291-1202R
C304 = CAP: Part #: 101782-1394R
C307 = CAP: Part #: 102058-1272R
C309 = CAP: Part #: 101782-1564R
C314 = CAP: Part #: 101782-1102R
L6 = INDUCTOR: Part #: 104227-0220R
L7 = INDUCTOR: Part #: 104288-0820R
Q1-Q4 = MOSFET_CSD16406Q3_0: Part #: 104283-0001R
R126 R127 = RESISTOR: Part #: 100687-1000R
R134 = RESISTOR: Part #: 104280-0005R
R135 = RESISTOR: Part #: 100830-0015R
R143 R147 = RESISTOR: Part #: 100642-4990R
R144 = RESISTOR: Part #: 102145-4993R
R145 R472 = RESISTOR: Part #: 102145-1603R
R146 = RESISTOR: Part #: 100642-8453R
R450 R451 R455-R457 R463 = RESISTOR: Part #: 101370-0001R
R453 = RESISTOR: Part #: 100687-1502R
R454 = RESISTOR: Part #: R0402-NOPOP
R461 = RESISTOR: Part #: 102145-2003R
R464 = RESISTOR: Part #: 102145-1503R
TP78 = TestPoint1_0: Part #: SMT-TP020
U23 = TPS43351QDAPRQ1_0: Part #: 104224-0001R

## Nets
1V8_I2C1_SCL: R708.1 U45.L1(I2C1_SCL_SCK) ; also on sheet 35
1V8_I2C1_SDA: R709.1 U45.L2(I2C1_SDA_SDI) ; also on sheet 35
GND: C7.2 C8.2 C13.2 C45.2 C47.2 C49.2 C50.2 C51.2 C52.2 C60.1 C61.1 C62.1 C63.1 C71.2 C72.2 C74.2 C76.1 C77.2 C78.1 C99.1 C100.1 C101.2 C102.1 C103.1 C115.2 C116.2 C130.2 C131.2 C132.2 C133.2 C134.2 C141.2 C142.2 C144.2 C151.2 C152.2 C153.2 C228.2 C229.2 C231.2 C232.2 C234.2 C235.2 C236.2 C295.1 C304.1 C305.2 C306.2 C309.1 C314.2 C326.1 C327.1 C328.1 C329.2 C330.2 C338.1 C341.1 C342.1 C346.1 C348.2 C349.1 C350.1 C352.2 C353.1 C354.1 C358.2 C375.1 C376.1 C377.1 C378.1 C379.1 C380.1 C381.1 C403.1 C407.1 C408.1 C409.1 C410.1 C421.2 C430.2 C431.2 C432.1 C433.2 C434.1 C435.2 C441.2 C459.1 C536.2 C565.2 C566.2 C567.2 C568.2 C575.2 C680.2 C683.2 C696.2 C715.2 C717.2 C718.2 C719.2 C785.2 C786.2 C789.1 C790.1 C792.2 C793.2 C794.2 C795.2 C796.2 C797.1 C798.2 C799.2 C800.1 C801.1 C810.1 E10.2 P1.17 P1.18 P1.41(G1) P1.42(G2) P1.43(G3) P1.44(G4) P12.1(SHIELD) Q3.1(S1) Q3.2(S2) Q3.3(S3) Q4.1(S1) Q4.2(S2) Q4.3(S3) R9.2 R10.2 R11.2 R83.1 R84.1 R85.1 R110.2 R111.2 R112.2 R116.2 R117.2 R118.2 R119.2 R120.2 R121.2 R122.2 R123.2 R124.2 R125.2 R145.1 R152.2 R191.2 R205.2 R206.2 R257.2 R260.2 R262.2 R266.2 R287.2 R333.2 R338.2 R455.1 R461.1 R463.1 R464.1 R472.1 R483.2 R513.2 R518.2 R529.2 R535.2 R537.2 R555.1 R565.2 R569.1 R570.2 R588.2 R589.2 R590.2 R591.2 R592.2 R599.1 R642.2 R643.2 R644.2 R675.2 R702.2 R838.2 R911.2 R915.2 R943.1 R946.1 R953.1 R954.1 R955.2 R958.2 SW4.1(A) SW4.2(AA) U3.15(RES0) U3.18(RES1(RES2)) U3.49(DAP(PWRPAD)) U6.3(GND) U8.4(TAB) U23.9(PGNDA) U23.19(AGND.1) U23.23(AGND.2) U23.30(PGNDB) U23.39(PWR_PAD) U37.2(GND) U44.2(GND) U45.A1(SUB_GND) U45.A4(REFGND1) U45.A7(GNDANA) U45.A13(SUB_GND) U45.B2(GPADC_IN0) U45.B10(SUB_GND) U45.B11(SUB_GND) U45.C2(GPADC_IN1) U45.C3(GPADC_IN2) U45.C12(SMPS12_FBK_GND) U45.D4(SMPS7_GND_1) U45.D5(SMPS7_GND_2) U45.D6(SUB_GND) U45.D7(SUB_GND) U45.D10(SMPS1_GND_1) U45.E4(SMPS7_GND_3) U45.E7(VAC/ACOK) U45.E8(SUB_GND) U45.E9(SMPS1_GND_2) U45.E10(SMPS1_GND_3) U45.F4(SMPS4_GND_1) U45.F5(AGND.1) U45.F6(SUB_GND) U45.F7(SUB_GND) U45.F9(SMPS2_GND_1) U45.F10(SMPS2_GND_2) U45.G4(SMPS4_GND_2) U45.G5(SMPS4_GND_3) U45.G7(SUB_GND) U45.G10(SMPS2_GND_3) U45.H4(SMPS5_GND_1) U45.H5(SMPS5_GND_2) U45.H6(SUB_GND) U45.H7(SUB_GND) U45.H10(SMPS3_GND_1) U45.J4(SMPS5_GND_3) U45.J6(SUB_GND) U45.J9(SMPS3_GND_2) U45.J10(SMPS3_GND_3) U45.K3(SMPS45_FDBK_GND) U45.L5(SMPS6_GND) U45.L6(SMPS6_GND_1) U45.L7(SMPS9_GND) U45.L8(SMPS9_GND_1) U45.L9(SMPS8_GND_1) U45.L10(SMPS8_GND) U45.M1(SUB_GND) U45.M2(SUB_GND) U45.M12(GND_DIG) U45.M13(AGND.2) U45.N1(SUB_GND) U45.N2(VIO_GND) U45.N13(SUB_GND) U55.2(GND) U55.3(ENn) U59.15(AVSS_ADC) U59.20(DRVSS.1) U59.21(DRVSS.2) U59.26(AVSS_DAC) U59.42(DVSS) U59.49(TPAD) U101.4(GND) U101.5(DIR) U102.2(GND) U132.3(PLL_AGND) U132.7(AGND) U132.19(DGND) U132.31(CH_AGND) U142.3(GND) U143.3(GND) ; also on sheet 3 5 7 8 9 11 12 13 14 15 16 17 18 19 20 21 22 24 25 28 29 31 32 33 34 35 36 49 50 51 52 55 57
VBATT_12V: F1.2 R453.2
VCC_SENSE: R549.2 U45.B3(VCC_SENSE)
VDD_???: U45.B1(SMPS7_FDBK) U45.L11(SMPS8_FDBK)
VDD_CORE: C326.2 L11.1 U45.K6(SMPS6_FBK) ; also on sheet 19
VDD_DDR: C350.2 L13.1 U45.K13(SMPS3_FDBK) ; also on sheet 17 24 25 26 28 29 30 50
VDD_DSPEVE_IVA_GPU: C349.2 C377.2 L14.1 L16.1 U45.K2(SMPS45_FDBK) ; also on sheet 19
VDD_MPU: C378.2 C410.2 L15.1 L17.1 R554.1 U45.B13(SMPS12_FBK) ; also on sheet 19
VDD_RTC: C102.2 R531.1 U45.A5(LDO9_OUT) ; also on sheet 13
VDDA_ANA: C680.1 U45.C8(LDOVANA_OUT)
VDDA_PHY_1V8: C352.1 U45.K11(LDO3_OUT) ; also on sheet 5 9 11
VDDA_PLL_1V8: C103.2 U45.B5(LDOLN_OUT) ; also on sheet 13 18
VDDA_RTC: C431.1 U45.A8(LDOVRTC_OUT) ; also on sheet 13
VDDS_1V8: C327.2 E10.3 L10.1 R192.1 U45.J8(SMPS9_FBK) ; also on sheet 9 16
VDDSHV5: C101.1 R530.1 U45.B6(LDO2_OUT) ; also on sheet 13 55
VDDSHV8: C430.1 U45.C6(LDO1_OUT) ; also on sheet 15
VIN1A_CLK0: R957.1
VIN1A_D0: RN32.4(R4A)
VIN1A_D1: RN32.3(R3A)
VIN1A_D2: RN32.2(R2A)
VIN1A_D3: RN32.1(R1A)
VIN1A_D4: RN33.4(R4A)
VIN1A_D5: RN33.3(R3A)
VIN1A_D6: RN33.2(R2A)
VIN1A_D7: RN33.1(R1A)
VIN1A_DE0: R947.1
VIN1A_FLD0: R950.1
VIN1A_HSYNC0: R948.1
VIN1A_VSYNC0: R949.1
AIC_BCLK: R253.2 R642.1 U59.38(BCLK)
AIC_DIN: R251.2 R643.1 U59.40(DIN)
AIC_DOUT: R250.2 U59.41(DOUT)
AIC_MCA3_ACLKX: R253.1
AIC_MCA3_AFSX: R252.1
AIC_MCA3_AXR0: R251.1
AIC_MCA3_AXR1: R250.1
AIC_MCLK: R254.1
AIC_WCLK: R252.2 U59.39(WCLK)
CPU_POR_RESETn: R596.1 U102.1(~{RESE}T) ; also on sheet 13
CPU_RESETn: R623.1
DBG_RX1: R106.1
DBG_TX1: U6.1(B) U6.2(A)
ENET_GPIO5_15: P1.1
ENET_GPIO5_16: P1.2
ENET_GPIO5_17: P1.4
ENET_GPIO5_20: P1.10
ENET_GPIO5_21: P1.7
ENET_GPIO5_22: P1.3
ENET_GPIO5_23: P1.6
ENET_GPIO5_24: P1.5
ENET_GPIO5_25: P1.8
ENET_GPIO5_26: P1.16
ENET_GPIO5_27: P1.13
ENET_GPIO5_28: P1.9
ENET_GPIO5_29: P1.12
ENET_GPIO5_30: P1.11
ENET_GPIO5_31: P1.14
ENET_RST_INn: R914.1 R915.1 U143.1(B)
ENET_RSTn: P1.15 U143.4(Y)
FTDI_RX: P1.19 R100.2
FTDI_TX: P1.21 R911.1 U142.1(B) U142.2(A)
GA1: R451.2 U23.6(GA1)
GA2: R457.2 U23.8(GA2)
GB1: R450.2 U23.33(GB1)
GB2: R456.2 U23.31(GB2)
GPMC_D00: R80.2 R110.1
GPMC_D01: R81.2 R111.1
GPMC_D02: R82.2 R112.1
GPMC_D03: J21.1 R113.2
GPMC_D04: R84.2 R114.2
GPMC_D05: J24.1 R115.2
GPMC_D06: R86.2 R116.1
GPMC_D07: R87.2 R117.1
GPMC_D08: R88.2 R118.1
GPMC_D09: R89.2 R119.1
GPMC_D10: R90.2 R120.1
GPMC_D11: R91.2 R121.1
GPMC_D12: R92.2 R122.1
GPMC_D13: R93.2 R123.1
GPMC_D14: R94.2 R124.1
GPMC_D15: R95.2 R125.1
H_RSTOUT_N: U59.33(~{RESET}) U132.8(RESETB) U143.2(A) ; also on sheet 13 21 22 52
I2C1_SCL: U59.1(SCL) ; also on sheet 35 52
I2C1_SDA: U59.2(SDA) ; also on sheet 35 52
I2C2_SCL: U3.8(SCL) U132.21(SCL) ; also on sheet 57
I2C2_SDA: U3.9(SDA) U132.22(SDA) ; also on sheet 57
I2C_EEPROM_WP: R569.2 R757.2 ; also on sheet 52
INIC_DBG_ERR_BOOTN: P1.29
INIC_DBG_RSTn: P1.31
INIC_TCK: P1.35
INIC_TDI: P1.39
INIC_TDO: P1.37
INIC_TMS: P1.33
LT_PMIC_RESET_OUT: R782.1 U101.3(A2)
MCASP1_ENn: R599.2 R766.2 ; also on sheet 34
MCU_DBG_RESETn: P1.24
MCU_EVT0: P1.28
MCU_FLMD0: P1.26
MCU_FLMD1: P1.20
MCU_RDY: P1.30
MCU_RESET_OUT: R940.1
MCU_TCK: P1.36
MCU_TDI: P1.40
MCU_TDO: P1.38
MCU_TMS: P1.34
MCU_TRSTn: P1.32
MCU_TVD: P1.22
MIC_IN+: R801.1 R802.1
MIC_IN-: R800.1
PHA: C300.1 L6.1 Q1.1(S1) Q1.2(S2) Q1.3(S3) Q3.5(D1) R126.2 U23.7(PHA)
PHB: C299.1 L7.1 Q2.1(S1) Q2.2(S2) Q2.3(S3) Q4.5(D1) R127.2 U23.32(PHB)
PMIC_32K_CLKOUT: U45.M11(CLK32KGO) ; also on sheet 35
PMIC_BOOT0: R518.1 R785.2 U45.L3(BOOT0)
PMIC_BOOT1: R513.1 R514.2 U45.K7(BOOT1)
PMIC_GPIO_0: R205.1 U45.B12(GPIO_0)
PMIC_GPIO_1: R191.1 R567.2 U45.C13(GPIO_1/VBUSDET)
PMIC_GPIO_2: R206.1 R783.1 U45.A12(GPIO_2/REGEN2)
PMIC_GPIO_3: R535.1 U45.H9(GPIO_3)
PMIC_GPIO_4_6: U45.K10(GPIO_4/SYSEN1) ; also on sheet 49
PMIC_GPIO_5: R565.1 U45.C10(GPIO_5/CLK32KGO)
PMIC_GPIO_6_4: U45.N11(GPIO_6/SYSEN2) ; also on sheet 51
PMIC_GPIO_7: R534.2 R537.1 U45.G9(GPIO_7/POWERHOLD)
PMIC_INT: U101.2(A1) ; also on sheet 13
PMIC_OFF: R211.1 ; also on sheet 13 55
PMIC_PWRDOWN: R483.1 R516.2 U45.K8(PWRDOWN)
PMIC_REGEN1: R784.1 TP41.1 U45.F8(REGEN1)
PMIC_RESET_IN: R153.2 R533.2 U37.1(~{RESE}T) U45.K9(RESET_IN)
PMIC_RESET_OUT: R782.2 R783.2 R784.2 ; also on sheet 13
PWRON: R208.2 R592.1 U45.G8(PWRON)
RPWRON: R194.2 R570.1 U45.C11(RPWRON)
RTC_PORZ: R530.2 U44.1(~{RESE}T) ; also on sheet 13
SMPS_7: C409.2 L18.1
SMPS_8: C328.2 L9.1
SW1: L17.2 U45.E11(SMPS1_SW_1) U45.E12(SMPS1_SW_2) U45.E13(SMPS1_SW_3)
SW2: L15.2 U45.F11(SMPS2_SW_1) U45.F12(SMPS2_SW_2) U45.F13(SMPS2_SW_3)
SW3: L13.2 U45.J11(SMPS3_SW_1) U45.J12(SMPS3_SW_2) U45.J13(SMPS3_SW_3)
SW4: L16.2 U45.G1(SMPS4_SW_1) U45.G2(SMPS4_SW_2) U45.G3(SMPS4_SW_3)
SW5: L14.2 U45.H1(SMPS5_SW_1) U45.H2(SMPS5_SW_2) U45.H3(SMPS5_SW_3)
SW6: L11.2 U45.M5(SMPS6_SW_1) U45.N5(SMPS6_SW)
SW7: L18.2 U45.D1(SMPS7_SW_1) U45.D2(SMPS7_SW_2) U45.D3(SMPS7_SW_3)
SW8: L9.2 U45.M10(SMPS8_SW) U45.N10(SMPS8_SW_1)
SW9: L10.2 U45.M7(SMPS9_SW) U45.N7(SMPS9_SW_1)
TPS43351_GC2: Q5.1(G) U23.4(GC2)
VAIC_AVDD_DAC3V3: C141.1 C142.1 C144.1 L21.1 U59.25(AVDD_DAC)
VAIC_DRVDD_3V3: C151.1 C152.1 C565.1 C566.1 C567.1 L22.1 U59.16(DRVDD.1) U59.17(DRVDD.2) U59.24(DRVDD.3)
VAIC_DVDD_1V8: C133.1 C134.1 U55.5(OUT) U59.36(DVDD.1)
VAIC_IOVDD_3V3: C130.1 C132.1 L19.2 U59.44(IOVDD)
VDAC_3V3: C131.1 C153.1 C536.1 L19.1 L21.2 L22.2 R249.1 R654.1 R659.1 R664.1 R668.1 U55.1(IN) ; also on sheet 49
VEVM_1V8: C800.2 C810.2 E10.1 L23.1 R842.2 R843.2 R844.2 R845.2 U132.20(DVDD) ; also on sheet 34 35
VEVM_3V3: C71.1 C74.1 C302.2 C330.1 C338.2 C341.2 C342.2 C346.2 C353.2 C354.2 C358.1 C375.2 C376.2 C379.2 C380.2 C381.2 C408.2 C441.1 C459.2 C683.1 C696.1 C785.1 C786.1 C801.2 L2.2 L3.1 R8.1 R20.1 R22.1 R80.1 R81.1 R82.1 R86.1 R87.1 R88.1 R89.1 R90.1 R91.1 R92.1 R93.1 R94.1 R95.1 R113.1 R114.1 R115.1 R134.1 R140.2 R143.2 R151.1 R153.1 R193.1 R194.1 R207.1 R208.1 R209.1 R332.1 R516.1 R534.1 R549.1 R583.1 R596.2 R623.2 R757.1 R766.1 R839.1 R840.1 R841.1 R912.1 R914.2 R944.1 R945.1 R959.2 U6.5(VCC) U23.11(SA2) U37.6(VDD) U44.6(VDD) U45.C4(LDO9_IN) U45.C5(LDOLN_IN) U45.D11(SMPS1_IN_1) U45.D12(SMPS1_IN_2) U45.D13(SMPS1_IN_3) U45.E1(SMPS7_IN_B1_1) U45.E2(SMPS7_IN_B1_2) U45.E3(SMPS7_IN_B1_3) U45.F1(SMPS4_IN_1) U45.F2(SMPS4_IN_2) U45.F3(SMPS4_IN_3) U45.G11(SMPS2_IN_1) U45.G12(SMPS2_IN_2) U45.G13(SMPS2_IN_3) U45.H11(SMPS3_IN_1) U45.H12(SMPS3_IN_2) U45.H13(SMPS3_IN_3) U45.J1(SMPS5_IN_1) U45.J2(SMPS5_IN_2) U45.J3(SMPS5_IN_3) U45.L12(LDO34_IN) U45.L13(LDO34_IN_1) U45.M6(SMPS6_IN) U45.M8(SMPS9_IN) U45.M9(SMPS8_IN) U45.N6(SMPS6_IN_1) U45.N8(SMPS9_IN_1) U45.N9(SMPS8_IN_1) U101.1(VCCA) U102.6(VDD) U132.10(IO_DVDD) U142.5(VCC) U143.5(VCC) ; also on sheet 3 12 13 21 22 31 32 33 34 35 49 51 52 55 56 57
VEVM_5V0: C72.1 C77.1 C99.2 C301.2 C407.2 R135.1 R138.2 R147.2 U23.28(SB2) U45.A6(LDO12_IN) U45.A9(LDOUSB_IN2) U45.A10(LDO7USB_IN1) ; also on sheet 31 32 33 36 49 55
VEVM_12V: C45.1 C47.1 C49.1 C50.1 C51.1 C52.1 C62.2 C63.2 Q1.5(D1) Q2.5(D1) Q5.3(S) U8.3 U23.38(VIN)
VID+: R943.2 R951.1
VID-: R955.1
VIDEO+: FL9.3
VIDEO-: FL9.2
VIO_PMIC: C434.2 C435.1 R192.2 R210.1 R533.1 U45.D9(VIO_IN) U101.8(VCCB)
VMCU_3V3: R913.1 ; also on sheet 55
VOUT1_CLK: U3.10(PCLK) ; also on sheet 58
VOUT1_D0: U3.43(B0/O4) ; also on sheet 58
VOUT1_D1: U3.44(B1/I2S_DB/O5) ; also on sheet 58
VOUT1_D2: U3.45(B2) ; also on sheet 12 58
VOUT1_D3: U3.46(B3) ; also on sheet 12 58
VOUT1_D4: U3.47(B4) ; also on sheet 12 58
VOUT1_D5: U3.48(B5) ; also on sheet 12 58
VOUT1_D6: U3.1(B6) ; also on sheet 12 58
VOUT1_D8: U3.35(G0/IO2) ; also on sheet 58
VOUT1_D9: U3.36(G1/IO3) ; also on sheet 58
VOUT1_D10: U3.37(G2) ; also on sheet 12 58
VOUT1_D11: U3.38(G3) ; also on sheet 12 58
VOUT1_D12: U3.39(G4) ; also on sheet 12 58
VOUT1_D13: U3.40(G5) ; also on sheet 12 58
VOUT1_D14: U3.41(G6) ; also on sheet 12 58
VOUT1_D15: U3.42(G7) ; also on sheet 12 58
VOUT1_D16: U3.25(R0/IO0) ; also on sheet 58
VOUT1_D17: U3.26(R1/IO1) ; also on sheet 58
VOUT1_D18: U3.27(R2) ; also on sheet 12 58
VOUT1_D19: U3.28(R3) ; also on sheet 12 58
VOUT1_D20: U3.29(R4) ; also on sheet 12 58
VOUT1_D21: U3.32(R5) ; also on sheet 12 58
VOUT1_D22: U3.33(R6) ; also on sheet 12 58
VOUT1_D23: U3.34(R7) ; also on sheet 12 58
VOUT1_DE: U3.5(DE) ; also on sheet 58
VOUT1_HSYNC: U3.3(HS) ; also on sheet 58
VOUT1_INTB: R846.1 ; also on sheet 58
VOUT1_VSYNC: U3.4(VS) ; also on sheet 58
VOUT_D7: U3.2(B7) ; also on sheet 12
VREVM_3V3: P1.23 P1.25 R912.2
VRMCU_3V3: P1.27 R913.2
VRTC_OUT: R514.1 R567.1 R785.1
VUSB_3V3: C433.1 U45.B9(LDOUSB_OUT) ; also on sheet 5
xtal1: C115.1 U45.A3(OSC16MIN) Y4.1(C1A) Y4.3(C2A)
xtal2: C116.1 U45.A2(OSC16MOUT) Y4.2(C1B) Y4.5(C2B)
N17043188: F1.1 Q5.4(D) U8.1
N17182406: TP78.1 U23.16(ENA) U23.17(ENB)
N17213676: R463.2 U23.22(RT)
N17213686: C60.2 R126.1
N17213736: C61.2 R127.1
N17213790: C299.2 U23.34(CBB)
N17213808: R138.1 U23.24(PGB)
N17213830: C78.2 R145.2 R146.1 U23.27(FBB)
N17213836: C303.2 C304.2 U23.26(COMPB)
N17213838: C301.1 L7.2 R135.2 U23.29(SB1)
N17213987: C295.2 R454.2 U23.35(VREG)
N17214057: Q2.4(G) R450.1
N17214061: R146.2 R147.1
N17214151: C300.2 U23.5(CBA)
N17214159: R140.1 U23.15(PGA)
N17214195: C76.2 R144.1 R472.2 U23.12(FBA)
N17214201: C307.2 C309.2 U23.13(COMPA)
N17214229: C302.1 L6.2 R134.2 U23.10(SA1)
N17214255: R454.1 R455.2 U23.20(SYNC)
N17214311: C305.1 U23.14(SSA)
N17214457: R453.1 U23.1(VBAT)
N17214562: C314.1 U23.21(DLYAB)
N17214601: Q1.4(G) R451.1
N17214615: C306.1 U23.25(SSB)
N17214651: R143.1 R144.2
N17551426: R209.2 R590.1 U45.D8(VBUS)
N17551447: U45.G6(RESET_OUT) U101.6(B2)
N17551455: C403.2 U45.C1(OSC16MCAP)
N17551519: R207.2 U45.A11(VCC_SENSE2)
N17551551: TP31.1 U45.J5(ENABLE1)
N17551822: R210.2 R589.1 TP43.1 U45.E6(NRESWARM)
N17551928: C100.2 U45.B7(VBG)
N18507369: C432.2 R193.2 U45.C7(VCC1)
N19066656: R591.1 TP42.1 U45.B8(SYNC_TO_EXCLOCK)
N20082076: TP30.1 U45.K1(INT) U101.7(B1)
N20307647: TP24.1 U45.J7(POWERGOOD)
N21135894: C647.2 P12.3(RING) R702.1
N21136021: R249.2 R644.1 U59.43(SELECT)
N21136029: R671.2 U59.11(MIC3L) U59.14(MIC3R)
N21136035: C558.1 C575.1 R673.1 R675.1 R801.2
N21136037: C568.1 R672.1 R673.2
N21136043: R672.2 U59.13(MICBIAS)
N21136051: C558.2 R671.1
N21136104: C173.2 U59.3(LINE1L+)
N21136106: C168.2 P12.2(TIP) R287.1
N21136118: R281.1 U59.29(LEFT_LO+)
N21136820: C648.1 R800.2
N21136921: R257.1 R654.2 U59.45(MFP0)
N21136923: R260.1 R659.2 U59.46(MFP1)
N21136925: R262.1 R664.2 U59.47(MFP2)
N21136935: R254.2 U59.37(MCLK)
N21136951: R266.1 R668.2 U59.48(MFP3)
N21137001: C173.1 R802.2
N21137040: C647.1 R697.2
N21137042: R697.1 U59.31(RIGHT_LO+)
N21137044: C168.1 R281.2
N21266752: C5.1 U3.20(DOUT+)
N21266761: C6.1 U3.19(DOUT-)
N21266764: C6.2 FL9.1
N21266767: C5.2 FL9.4
N21299491: C798.1 R956.2 U132.5(XTAL1/OSC) Y7.2
N21299495: C799.1 R956.1 U132.6(XTAL2) Y7.1
N21300352: R948.2 U132.25(HSYNC)
N21300357: R949.2 U132.24(VSYNC/PALI)
N21300366: RN32.5(R4B) U132.18(YOUT0)
N21300375: RN32.6(R3B) U132.17(YOUT1)
N21300384: RN32.7(R2B) U132.16(YOUT2)
N21300398: RN32.8(R1B) U132.15(YOUT3)
N21300482: RN33.5(R4B) U132.14(YOUT4)
N21300487: RN33.6(R3B) U132.13(YOUT5)
N21300492: RN33.7(R2B) U132.12(YOUT6)
N21300497: R958.1 R959.1 RN33.8(R1B) U132.11(YOUT7/I2CSEL)
N21300502: R957.2 U132.9(SCLK)
N21300554: C788.2 U132.1(AIP1A)
N21300935: C789.2 C791.1 U132.30(REFM)
N21300940: C790.2 C791.2 U132.29(REFP)
N21301555: C792.1 C793.1 C794.1 L23.2 U132.4(PLL_AVDD) U132.32(CH_AVDD)
N21361557: C648.2 U59.4(LINE1L-)
N21411928: R332.2 R333.1 U3.24(MODE_SEL(VODSEL))
N21411951: R944.2 U132.28(PDN)
N21411993: R945.2 R946.2 U132.27(INTREQ/GPCL/VBLK)
N21412338: R947.2 U132.26(AVID)
N21412343: R950.2 U132.23(FIG/GLCO)
N21412499: C797.2 U132.2(AIP1B)
N21415881: C788.1 R952.2 R954.2
N21415900: C796.1 L25.2 R952.1
N21415906: C795.1 L24.1 R951.2 R953.2
N21415919: C715.1 L24.2 L25.1
N21756433: R22.2 R838.1 R846.2 U3.31(INTB(BISTEN))
N21756809: R11.1 R841.2 U3.13(I2S_CLK/O8(CFG1))
N21756816: R9.1 R839.2 U3.12(I2S_WC/O7(CFG0))
N21756819: R10.1 R840.2 U3.11(I2S_DA/O6(RFB))
N21757005: C7.1 C719.1 R844.1 U3.17(CAPHS12(VDDHS))
N21757009: C13.1 C234.1 C718.1 R843.1 U3.7(CAPL12(VDDL))
N21757015: C8.1 C717.1 R842.1 U3.14(CAPP12(VDDP))
N21757246: C229.1 C231.1 L2.1 R845.1 U3.22(VDD33(VDDTX))
N22626207: R106.2 U142.4(Y)
N22626247: R100.1 U6.4(Y)
N22765820: R583.2 R940.2 SW4.3(B) SW4.4(BB) U102.3(~{MR})
N22899654: C307.1 R464.2
N22899655: C303.1 R461.2
N22964373: J21.2 R83.2
N22964378: J24.2 R85.2
N24686365: R151.2 R152.1 U37.5(SENSE1)
N24686375: C329.1 U37.4(CT)
N24700289: R554.2 R555.2 U102.5(SENSE1)
N24700307: C421.1 U102.4(CT)
N32742919: C235.1 C236.1 L3.2 U3.30(VDDIO)
N32835273: C232.1 U3.23(CMF(DE-EMPH))
N32916975: R20.2 R338.1 U3.6(IDX)
N33161549: C228.1 R8.2 U3.21(PDB)
N35662197: TP32.1 U45.N12(VPROG/TESTV)
N42624965: R211.2 R588.1 U45.E5(NSLEEP)
N43640412: R529.1 R531.2 U44.5(SENSE1)
N43640433: C348.1 U44.4(CT)
N45361223: Q3.4(G) R457.1
N45364158: Q4.4(G) R456.1
N47347830: R709.2 U45.H8(I2C2_SDA_SDO)
N47347885: R708.2 U45.M3(I2C2_SCL_SCE)

Not connected (* = marked no-connect by the designer): P12 4(TIPB) 5(MH1) 6(MH2); U3 16(NC.16(RES1)); U23 2(NC.2) 3(NC.3) 18(NC.18) 36(NC.36) 37(EXTSUP); U37 3(~{MR}); U44 3(~{MR}); U45 B4(GPADC_REF) C9(NC4)* K4(NC2)* K5(NC5)* K12(NC1)* L4(NC3)* M4(NC6)* N3(NC7)* N4(NC8)*; U55 4(NC/FB)*; U59 5(LINE1R+) 6(LINE1R-) 7(LINE2L+) 8(LINE2L-) 9(LINE2R+) 10(LINE2R-) 12(MICDET) 18(HPLOUT) 19(HPLCOM) 22(HPRCOM) 23(HPROUT) 27(MONO_LO+) 28(MONO_LO-) 30(LEFT_LO-) 32(RIGHT_LO-) 34(GPIO2) 35(GPIO1); Y4 4(NC.4) 6(NC.6)

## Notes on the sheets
sheet 37
- TI CONFIDENTIAL - NDA RESTRICTIONS
- Work - In - Progress
- DEFAULT CONFIGURED FOR 905
- Preliminary Information - Subject to change
sheet 38
- TI CONFIDENTIAL - NDA RESTRICTIONS
- Work - In - Progress
- SINGLE POINT CONTACT
- CIRCUIT ADAPTED FROM JAMR2 RADIO REFERENCE
- Preliminary Information - Subject to change
sheet 39
- TI CONFIDENTIAL - NDA RESTRICTIONS
- Work - In - Progress
- OPTIONAL
- Preliminary Information - Subject to change
sheet 40
- TI CONFIDENTIAL - NDA RESTRICTIONS
- PMIC HAS DUAL FOOTPRINT
  FOR 32678 HERTZ AND 16.384
  MHZ CRYSTAL
- PMIC_VIO IS 1.8 VOLTS
  NOT THIS MEANS TRANSLATORS FOR I2C AND OTHERS
- REV D
- Work - In - Progress
- PULLUP ON PWRDOWN TURNS
  OFF PMIC. DRIVE LOW TO
  ENABLE.
- BOOT0 low = Vayu sequence
  BOOT0 high PMIC RESET_OUT pulse mode
  BOOT1 = always low.
- Preliminary Information - Subject to change
sheet 41
- TI CONFIDENTIAL - NDA RESTRICTIONS
- Work - In - Progress
- (NOT BEING USED??)
- Preliminary Information - Subject to change
sheet 42
- TI CONFIDENTIAL - NDA RESTRICTIONS
- Work - In - Progress
- REMOTE SENSING
- REMOTE SENSING
- NOTE INDUCTORS HAVE AUTOMOTIVE AND
  COMMERICAL PART NUMBERS ONE APPLIED AT
  THIS TIME
- FOR REPACKAGED TWL PART USE 22uF
  FOR  PRODUCTION PART USE 47uF CAPS
  ON ALL SMPS OUTPUTS C1210
  FOOTPRINT
- REMOTE SENSING
- REMOTE SENSING
- REMOTE SENSING
- Preliminary Information - Subject to change
sheet 43
- TI CONFIDENTIAL - NDA RESTRICTIONS
- REMOTE SENSING
- Work - In - Progress
- REMOTE SENSING
- REMOTE SENSING
- REMOTE SENSING
- Preliminary Information - Subject to change
sheet 44
- TI CONFIDENTIAL - NDA RESTRICTIONS
- REV D1
- Work - In - Progress
- OPTION TO HAVE MCU ASSERT VAYU POR
- Preliminary Information - Subject to change
sheet 45
- TI CONFIDENTIAL - NDA RESTRICTIONS
- Work - In - Progress
- SYSBOOT-0
- SYSBOOT-1
- SYSBOOT-2
- SYSBOOT-3
- SYSBOOT-4
- SYSBOOT-5
- SYSBOOT-6
- SYSBOOT-7
- BOOT MODES:
     EMMC 11 1000 (default)
     SD   11 0000
     USB  01 0000
- 10000001-EVM
- Preliminary Information - Subject to change
sheet 46
- TI CONFIDENTIAL - NDA RESTRICTIONS
- GHS PROBE
- MOST PROBE
- Work - In - Progress
- QTE/FSI CONNECTOR
- FTDI RX/TX??
- AR8031 PHY/RJ45
- DEBUG ADAPTER
- OPTION TO HOLD PHY IN RESET.
- PLAN IS TO CONNECT RGMI TO AN
  AR8031 PHY IN RGMII MODE.  IF WE
  RUN INTO SIGNAL ISSUES THEN WILL
  DOWNGRADE TO MII.
- Preliminary Information - Subject to change
sheet 47
- TI CONFIDENTIAL - NDA RESTRICTIONS
- Work - In - Progress
- Preliminary Information - Subject to change
sheet 48
- TI CONFIDENTIAL - NDA RESTRICTIONS
- Work - In - Progress
- 10TPB100ML
- 10 Volts
- Less than ESR 35m-ohm
- POSSIBLE HIGHER VOLTAGE RANGE ON C63
- Fsw = 400KHZ
- 10 Volts
- Less than ESR 35m-ohm
- GRM32ER61A476KE20L (1210-10V)
  T525D476M016ATE035 (7343-16V)
- 100uF total
- Preliminary Information - Subject to change
